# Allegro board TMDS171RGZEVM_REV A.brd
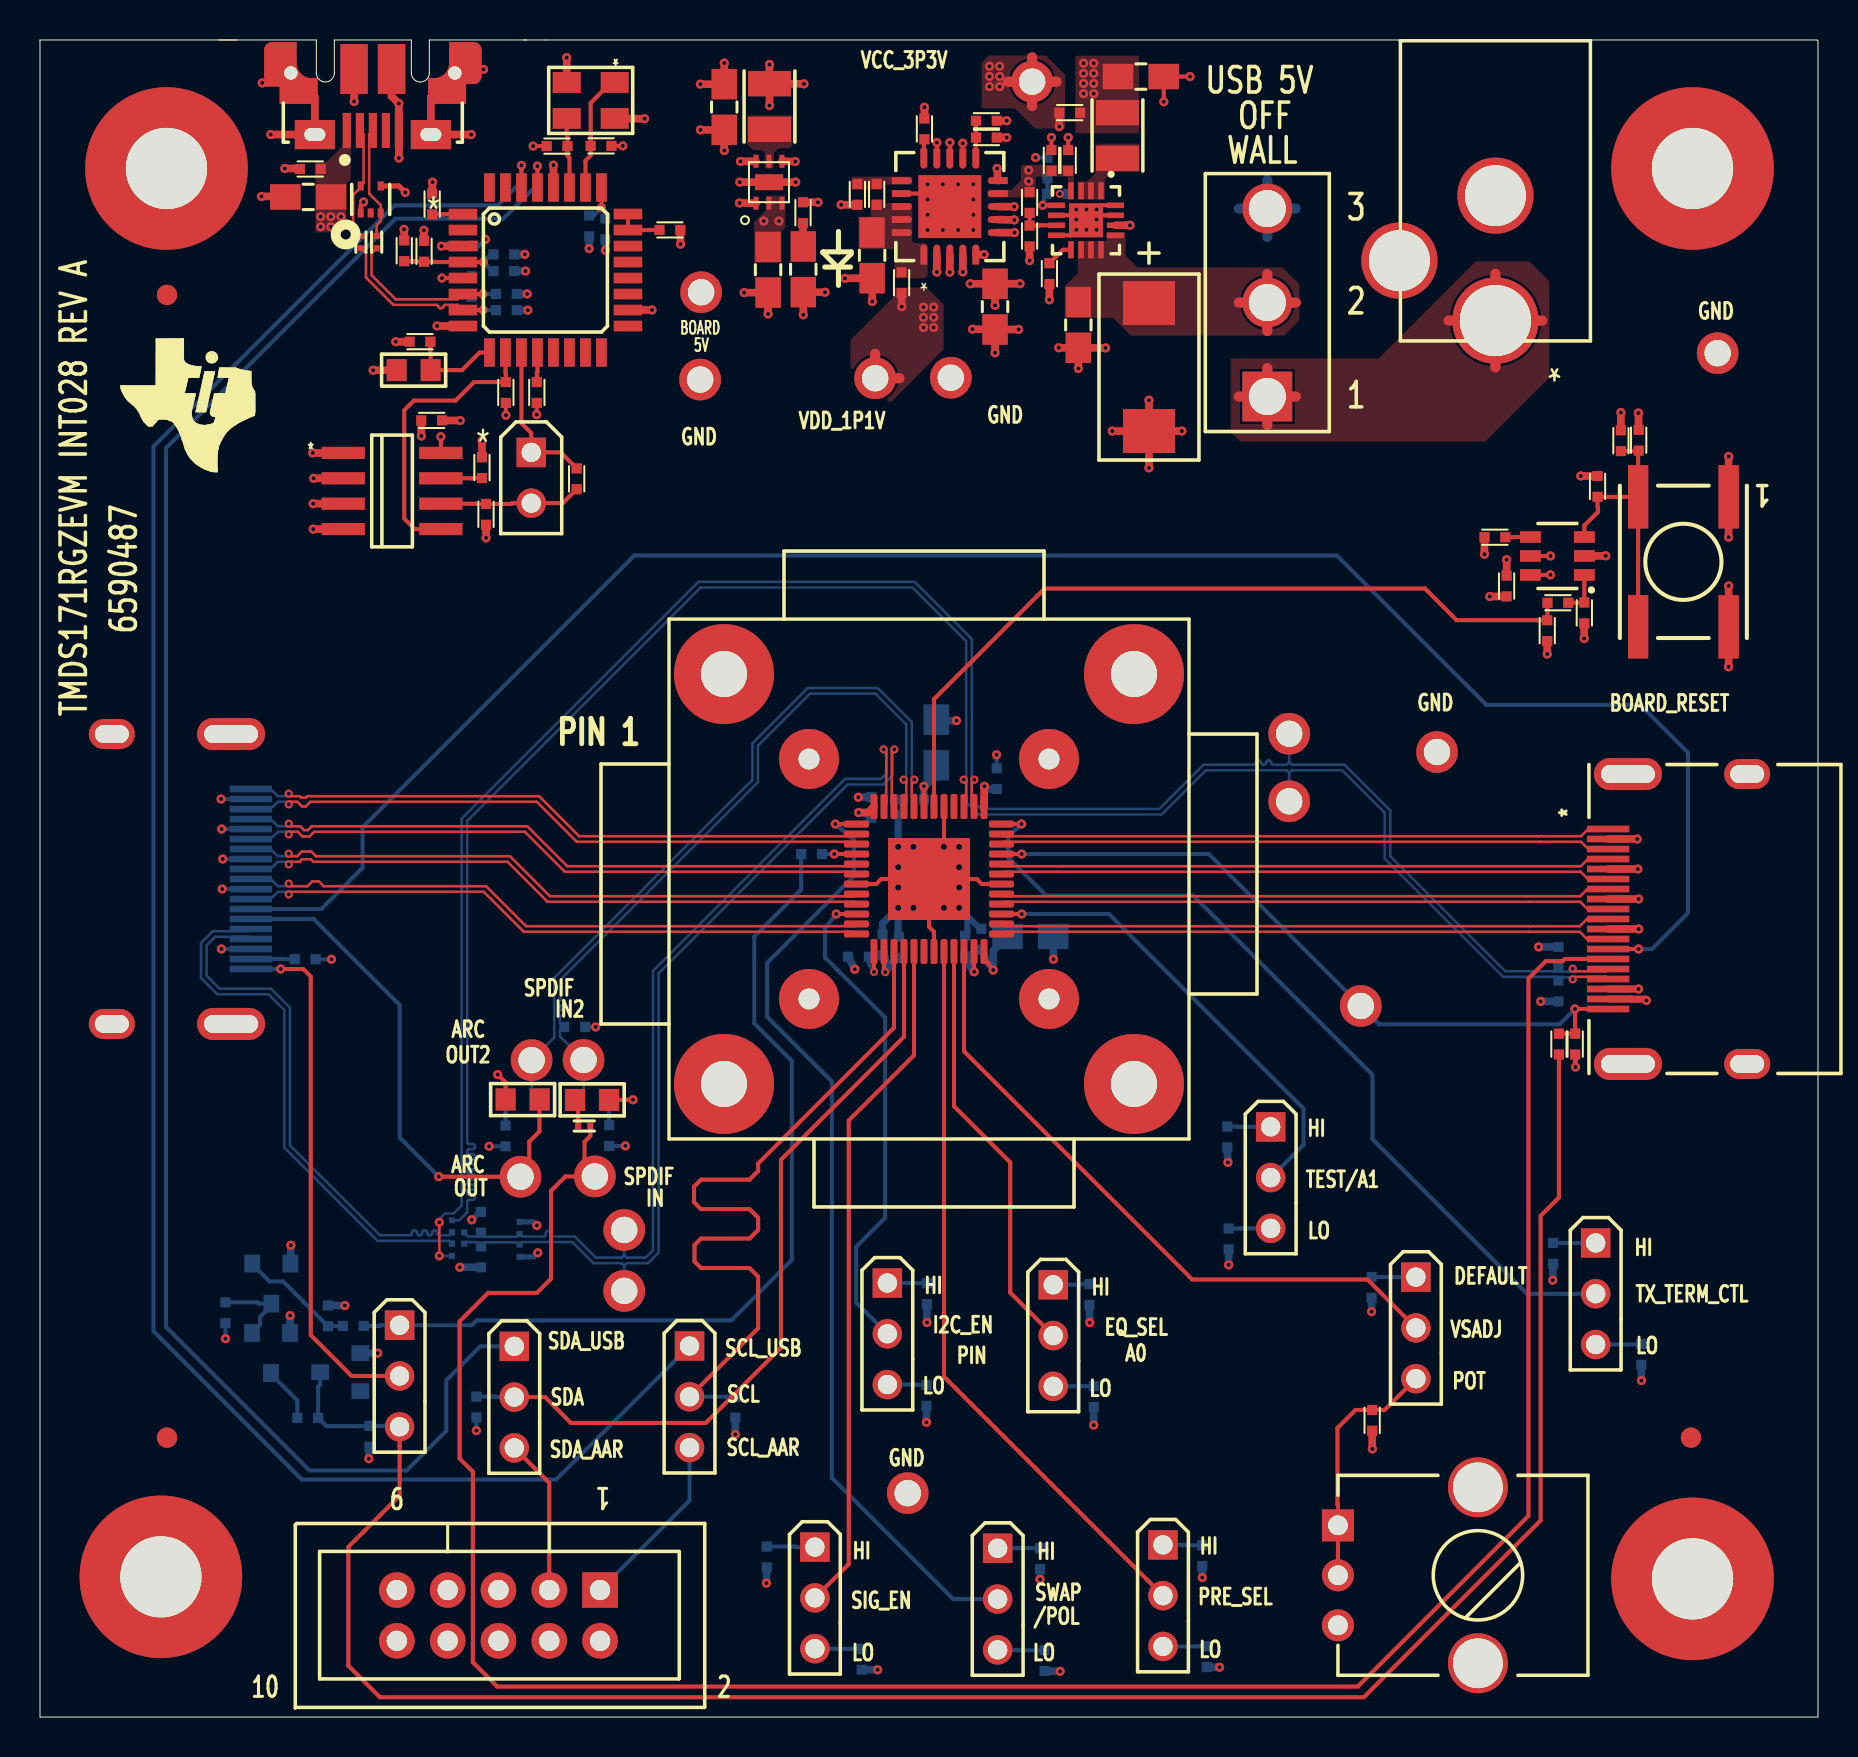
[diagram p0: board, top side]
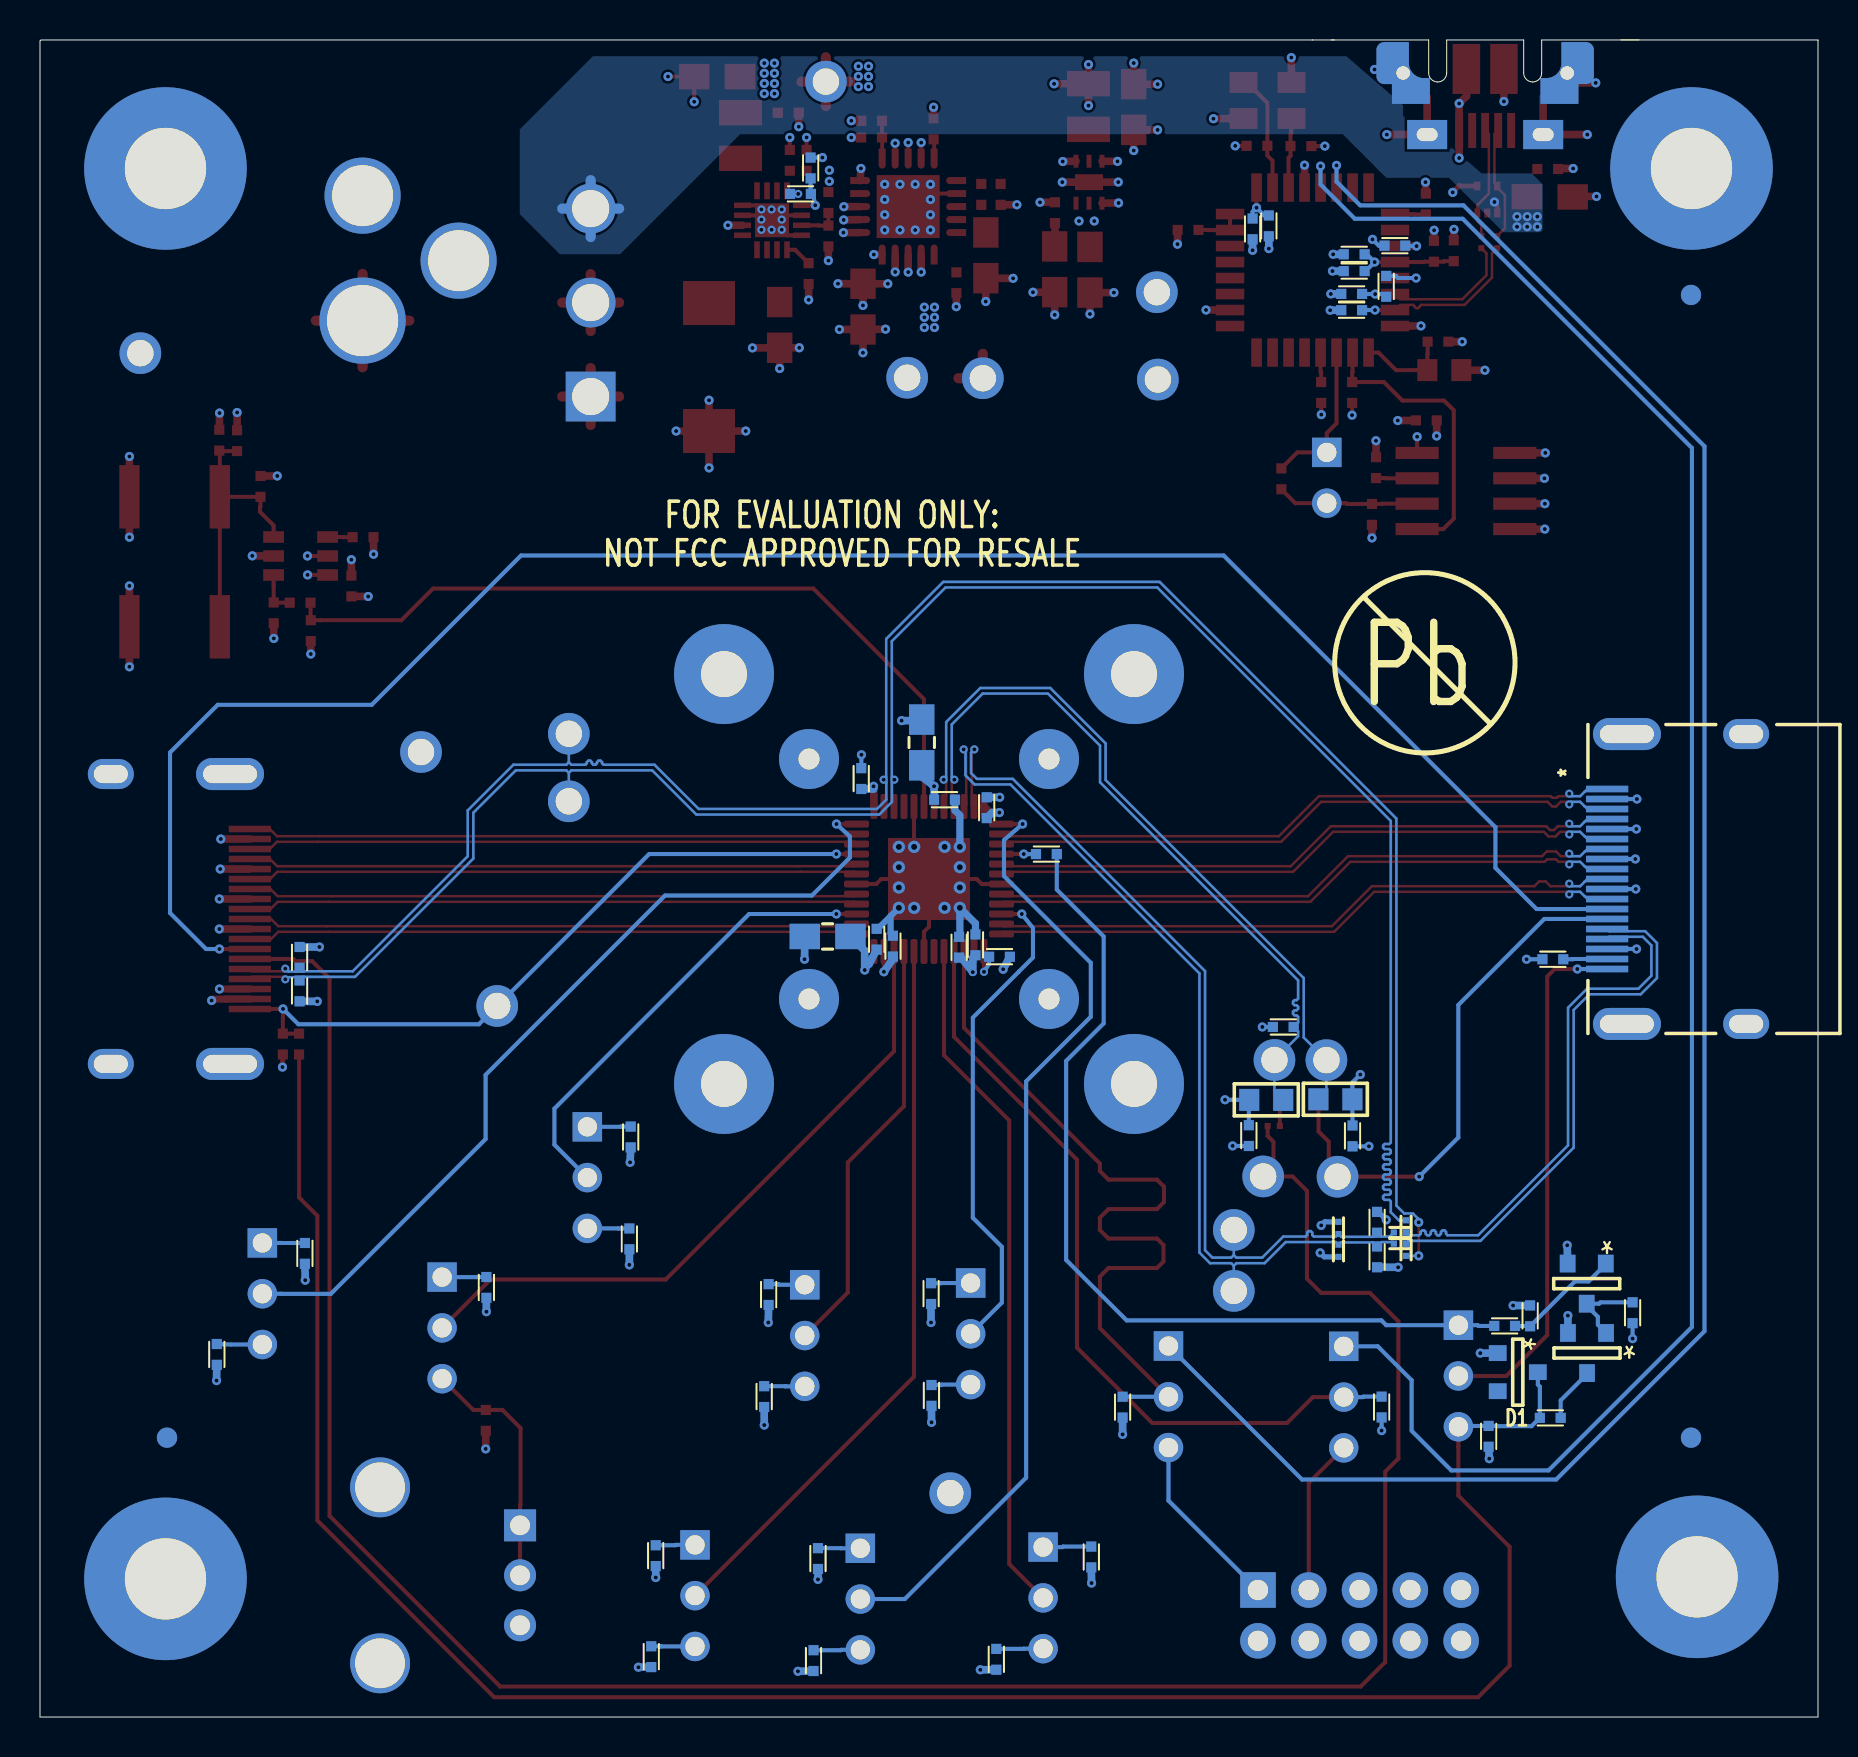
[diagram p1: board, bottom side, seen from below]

Outline 88.9 x 83.87 mm; copper layers: TOP, L2, L3, L4, L5, BOTTOM. Coordinates in mm from the lower left corner of the outline.
Outline path: 9.85,83.87 0,83.87 0,0 88.9,0 88.9,83.82 88.85,83.87 25.25,83.87 ; 25.3,83.87 24.18,83.87

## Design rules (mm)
net group DIFFPAIR12: nets OUT_D2N OUT_D2P
net group DIFFPAIR13: nets OUT_D1N OUT_D1P
net group DIFFPAIR14: nets OUT_D0N OUT_D0P
net group DIFFPAIR15: nets OUT_CLKN OUT_CLKP
net group DIFFPAIR16: nets IN_D0N IN_D0P
net group DIFFPAIR17: nets IN_D1N IN_D1P
net group DIFFPAIR18: nets IN_D2N IN_D2P
net group DIFFPAIR19: nets IN_CLKN IN_CLKP
net group DIFFPAIR24: nets SCL_SRC SDA_SRC
net group DIFFPAIR25: nets HDMI_SCL_SRC HDMI_SDA_SRC
net group DIFFPAIR27: nets N16919318 N16919400
net group DIFFPAIR29: nets AUX_SRCN/ARC_OUT AUX_SRCP/SPDIF_IN
net group DP1: nets N17024118 N17024121
net group DP2: nets HDMI_SCL_SRC_IN HDMI_SDA_SRC_IN
net group DIFF_PAIR 100 OHM_PH: nets EQ_SEL_A0 HDMI_SEL#_TEST_A1 I2C_EN_PIN OE PRE_SEL SCL_CTL_USB SDA_CTL_USB SIG_EN SWAP/POL TX_TERM_CTL VSADJ
nets with their own width: min track width 0.203; nets X2

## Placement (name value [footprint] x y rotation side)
C4  1 uF  [0603]  24.98 30.89 180 bottom
C5  1 uF  [0603]  26.74 30.86 0 bottom
C6  1 uF  [0603]  24.98 30.88 180 top
C7  1 uF  [0603]  28.46 30.86 180 top
C8  10uF  [0805]  44.81 48.74 90 bottom
C9  0.1uF  [0402]  40.93 38.02 180 bottom
C10  0.1uF  [0402]  43.67 45.88 180 bottom
C17  0.1uF  [0402]  47.07 38.9 90 bottom
C18  0.1uF  [0402]  41.56 45.48 90 bottom
C19  0.1uF  [0402]  46.25 38.55 90 bottom
C20  10uF  [0805]  49.52 39.04 0 bottom
C21  0.1uF  [0402]  42.95 38.5 90 bottom
C22  0.01uF  [0402]  42.13 38.62 90 bottom
C23  0.1uF  [0402]  47.84 46.93 90 bottom
C26  DNI_200nF  [0402]  75.36 54.33 270 top
C27  18pF  [0402]  79.04 63.83 90 top
C28  220pF  [0402]  72.75 59 180 top
C29  0.1uF  [0402]  73.33 56.57 270 top
C30  330uF  [7343]  55.45 70.71 270 top
C31  10uF  [0805]  51.92 69.62 270 top
C32  22uF  [0805]  55.04 82.04 0 top
C34  3.3 nF  [0402]  50.47 72.19 270 top
C35  10uF  [0805]  47.75 70.54 270 top
C36  10uF  [0805]  41.61 73.1 270 top
C37  0.01uF  [0402]  47.32 78.99 0 top
C38  DNI  [0402]  44.22 79.43 90 top
C39  2.2uF  [0805]  13.41 76.02 180 top
C40  0.1uF  [0402]  27.46 74.57 90 bottom
C41  0.01uF  [0402]  28.27 74.42 90 bottom
C42  0.01uF  [0402]  21.16 73.58 180 bottom
C45  22pF  [0402]  23.32 71.17 0 bottom
C46  0.1uF  [0402]  23.19 73.15 180 bottom
C47  0.01uF  [0402]  23.19 72.31 180 bottom
C49  22pF  [0402]  23.32 70.36 180 bottom
C50  33pF  [0402]  28.05 78.58 0 top
C51  33pF  [0402]  25.85 78.56 180 top
C52  1 uF  [0603]  17.83 67.36 0 top
C57  10uF  [0805]  36.4 72.38 270 top
C58  2.2uF - DNI  [0805]  34.21 80.52 270 top
C59  0.1uF  [0402]  19.58 64.85 0 top
C60  0.1uF  [0402]  13.51 77.42 180 top
D1  Zener 6V  [SOT_23_321]  15.01 17.25 270 bottom
D2  LED Green 0805  [0805]  38.16 72.4 270 top
J1  HDR3X1 M .1  [HDR_THVT_1X3_100]  17.98 19.6 0 top
J3  HDR3X1 M .1  [HDR_THVT_1X3_100]  42.37 21.7 0 top
J4  HDR3X1 M .1  [HDR_THVT_1X3_100]  32.48 18.55 0 top
J5  Header 5x2 0.1" thru-hole  [CON_THVT_SHRD_2X5_100_M]  20.38 5.08 180 top
J6  HDR3X1 M .1  [HDR_THVT_1X3_100]  23.71 18.54 0 top
J7  HDR3X1 M .1  [HDR_THVT_1X3_100]  61.53 29.52 0 top
J8  HDR3X1 M .1  [HDR_THVT_1X3_100]  68.8 22 0 top
J9  2.1mm x 5.5mm  [PJ-202AH]  72.77 69.84 180 top
J11  HDR3X1 M .1  [HDR_THVT_1X3_100]  38.75 8.5 0 top
J12  HDR3X1 M .1  [HDR_THVT_1X3_100]  50.66 21.62 0 top
J13  USB Micro B  [USB_SMRT_MICRO-B_FCI]  16.64 82.22 180 top
J14  HDR3X1 M .1  [HDR_THVT_1X3_100]  77.78 23.71 0 top
J15  HDR3X1 M .1  [HDR_THVT_1X3_100]  56.15 8.61 0 top
J17  HDR3X1 M .1  [HDR_THVT_1X3_100]  47.88 8.44 0 top
JP1  JUMPER  [HDR_THVT_1X2_100]  24.56 63.25 0 top
L1  2.2 uH  [IND_1008]  53.87 79.1 90 top
L2  1 uH - DNI  [IND_1008]  36.47 80.54 270 top
LP1  LP  [TESTLOOP]  24.58 32.85 0 top
LP2  LP  [TESTLOOP]  27.18 32.86 180 top
LP3  LP  [TESTLOOP]  24.02 27.02 0 top
LP4  LP  [TESTLOOP]  27.74 27.04 180 top
LP5  LP  [TESTLOOP]  49.61 81.79 0 top
LP6  LP  [TESTLOOP]  41.76 66.95 0 top
LP7  LP  [TESTLOOP]  45.54 66.98 0 top
LP8  LP  [TESTLOOP]  69.85 48.26 0 top
LP9  LP  [TESTLOOP]  43.39 11.2 0 top
LP10  LP  [TESTLOOP]  62.46 49.17 0 top
LP11  LP  [TESTLOOP]  62.46 45.8 0 top
LP12  LP  [TESTLOOP]  33.06 71.26 0 top
LP13  LP  [TESTLOOP]  66.04 35.56 0 top
LP14  LP  [TESTLOOP]  33.01 66.89 0 top
LP15  LP  [TESTLOOP]  29.21 21.31 0 top
LP16  LP  [TESTLOOP]  29.21 24.36 0 top
LP17  LP  [TESTLOOP]  83.88 68.21 0 top
NOREF  -  []  9.87 -39.35 0 top
NOREF#2  -  [unnamed#2]  6.32 77.44 0 top
NOREF#3  -  [unnamed#2]  82.63 77.44 0 top
NOREF#4  -  [unnamed#2]  6.05 7.01 0 top
NOREF#5  -  []  0 0 90 top
NOREF#6  -  [unnamed#2]  82.63 6.91 0 top
NOREF#7  -  [unnamed#2]  82.55 13.97 0 top
NOREF#8  -  [unnamed#2]  6.35 13.97 0 top
NOREF#9  -  []  4.01 62.26 0 top
NOREF#10  -  []  0 0 0 top
NOREF#11  -  [unnamed#2]  6.35 71.12 0 top
NOREF#12  -  [unnamed#2]  6.35 71.12 180 bottom
NOREF#13  -  [unnamed#2]  6.35 13.97 180 bottom
NOREF#14  -  []  78.45 61.77 180 bottom
NOREF#15  -  []  19.66 52.72 180 bottom
NOREF#16  -  [unnamed#2]  82.55 13.97 180 bottom
P1  HDMI_IN  [CON_HDMI_SD-47151-001]  10.54 41.91 90 bottom
P2  HDMI_OUT  [CON_HDMI_SD-47151-001]  78.41 39.91 90 top
Q1  FDV301N_NFET_8V  [SOT_23_321]  11.56 21.67 0 bottom
Q2  FDV301N_NFET_8V  [SOT_23_321]  11.55 18.2 0 bottom
R5  100  [0402]  15.67 19.56 180 bottom
R10  1K  [0402]  16.47 14.04 270 bottom
R11  1K  [0402]  9.27 20.22 270 bottom
R12  100K  [0402]  14.39 20.06 270 bottom
R13  10  [0402]  13.39 14.96 0 bottom
R16  47K  [0402]  22.05 23.01 270 bottom
R17  47K  [0402]  22.05 24.74 90 bottom
R24  0  [0201]  20.9 23.67 180 bottom
R25  0  [0201]  20.9 24.23 180 bottom
R34  0  [0201]  27.21 29.56 180 top
R35  DNI  [0402]  23.27 29.06 90 bottom
R36  75  [0402]  28.46 29.08 90 bottom
R45  47K  [0402]  75.92 37.99 90 bottom
R46  47K  [0402]  75.92 36.31 270 bottom
R57  65K  [0402]  44.35 21.17 90 bottom
R58  2K  [0402]  34.77 15.5 90 bottom
R59  2K  [0402]  21.82 15.5 90 bottom
R60  65K  [0402]  44.33 16.08 270 bottom
R61  65K  [0402]  50 7.92 90 bottom
R62  65K  [0402]  50.22 2.82 270 bottom
R63  65K  [0402]  58.11 8.07 90 bottom
R64  65K  [0402]  58.34 3.02 270 bottom
R66  65K  [0402]  59.37 29.01 90 bottom
R68  65K  [0402]  52.47 21.13 90 bottom
R69  65K  [0402]  59.43 23.91 270 bottom
R70  65K  [0402]  52.69 16.02 270 bottom
R71  65K  [0402]  36.34 8 90 bottom
R72  65K  [0402]  75.66 23.19 90 bottom
R73  65K  [0402]  41.08 2.89 270 bottom
R74  65K  [0402]  80.06 18.13 270 bottom
R75  7K  [0402]  66.58 21.48 90 bottom
R76  PTV09 10K POT-DNI  [VAR_RES_THVT_PTV09A-1_123]  64.9 7.09 270 top
R77  0  [0402]  75.9 55.73 0 top
R78  10K  [0402]  77.22 55.22 90 top
R79  4.7K  [0402]  79.93 63.86 270 top
R80  0  [0402]  77.88 61.54 90 top
R81  100K  [0402]  51.41 77.85 270 top
R82  500  [0402]  38.15 75.23 90 top
R83  0  [0402]  49.48 75.74 90 top
R84  0  [0402]  51.49 80.24 0 top
R85  750K  [0402]  50.37 77.47 90 bottom
R86  240K  [0402]  50.88 76.17 180 bottom
R87  DNI  [0402]  50.57 77.85 270 top
R88  4.7K  [0402]  47.32 79.83 180 top
R89  0  [0402]  43.08 71.73 90 top
R90  1.87K  [0402]  41.83 76.15 270 top
R91  4.42K  [0402]  40.87 76.15 90 top
R92  DNI  [0402]  18.21 73.33 90 top
R93  DNI  [0402]  19.2 73.3 270 top
R94  1.5K  [0402]  21.59 71.55 270 bottom
R95  33  [0201]  16.05 73.76 90 top
R96  33  [0201]  16.83 73.76 90 top
R98  10K  [0402]  31.5 74.37 180 top
R99  1K  [0402]  23.29 66.24 90 top
R100  1K  [0402]  22.3 60.15 90 top
R101  1K  [0402]  19.61 75.67 90 top
R102  10K  [0402]  24.84 66.24 90 top
R103  15K  [0402]  19 68.78 0 top
R104  0  [0402]  13.26 37.9 180 bottom
R115  47K - DNI  [0402]  66.61 14.84 270 top
R120  DNI  [0402]  49.48 74.07 270 top
R121  1K  [0402]  22.1 62.48 90 top
R122  0  [0402]  26.83 61.92 270 top
R123  0  [0201]  20.6 24.54 90 bottom
R124  0  [0201]  20.6 23.37 270 bottom
R125  0  [0201]  23.98 24.46 90 bottom
R126  0  [0201]  23.98 23.32 270 bottom
R127  500K  [0402]  26.74 34.51 180 bottom
R129  0  [0402]  75.95 33.66 270 top
R130  1K  [0402]  76.76 33.66 270 top
R131  0  [0402]  38.58 43.16 180 bottom
SW1  PB_SWITCH  [SW_MOM_2NO]  82.17 57.77 180 top
SW2  3POS - SPDT  [SW_THVT_SPDT_3_185P]  61.37 70.74 0 top
U1  TMDS181RGZ  [RGZ48_GRYPHICS_48QFN07-0P5]  44.45 41.91 0 top
U3  TPS3808  [DBV_R-PDSO-G6]  75.87 58.06 180 top
U4  TPS62150A  [RGT_QFN-16]  52.3 74.85 270 top
U5  TPS74201RGWT  [QFN_20_203X203_26]  45.49 75.54 90 top
U6  TPS61240 - DNI  [DRV_S-PWSON-N6]  36.45 76.76 90 top
U7  TUSB3410  [PQFP_32_7P2X7P2_P8MM]  25.27 72.36 0 top
U8  24LC256  [SOIC_8_197X157_50]  17.6 61.32 0 top
U16  TPD2E001  [DRL_PSDO_5]  16.54 75.9 90 top
Y1  12 MHz  [XTAL_4_SM_126X98]  27.53 80.85 180 top

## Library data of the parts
C4-C10 C17-C23 C26-C29 C31 C32 C34 C37-C42 C45-C47 C49-C52 C57-C60 = CAP NP
C30 = CAPACITOR POL
C35 C36 = CAP_0
D1 = Zener 6V
D2 = DIODE
J1 J3 J4 J6-J8 J11 J12 J14 J15 J17 = HDR3X1 M _2.1
J5 = CONN PCB 5x2-S
J9 = BNC_2
J13 = USB Mini AB_1
JP1 = JUMPER
L1 L2 = INDUCTOR
LP1-LP17 = TESTLOOP
P1 P2 = CONN HDMI TYPE A
Q1 Q2 = FDV301N_NFET_8V
R5 R10-R13 = r0402
R16 R17 R24 R25 R34-R36 R45 R46 R57 R61-R64 R66 R68-R75 R77-R81 R83-R87 R89 R92-R96 R98-R104 R115 R120-R127 R129-R131 = R
R58-R60 R82 R88 R90 R91 = R_4
R76 = POT
SW1 = PB_SWITCH_0
SW2 = SW_SLIDE_SPDT2
U1 = DP159RGZ_8
U3 = TPS3808DBV
U4 = TPS62150A
U5 = TPS74401RGWT_1
U6 = TPS61420
U7 = TUSB3410_3
U8 = I2C_0
U16 = TPD2E001-Q1
Y1 = CRYSTAL14_0

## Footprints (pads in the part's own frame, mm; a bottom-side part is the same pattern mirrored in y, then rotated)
0201
  rect 0.305x0.305 smd: 1(-0.305,0) 2(0.305,0)
0402
  rect 0.508x0.508 smd: 1(-0.521,0) 2(0.521,0)
0603
  rect 1x1.1 smd: 1(0,0) 2(1.7,0)
0805
  rect 1.524x1.27 smd: 1(-1.143,0) 2(1.143,0)
7343
  rect 2.2x2.6 smd: 1(0,0) 2(6.4,0)
CON_HDMI_SD-47151-001
  rect 0.33x2.11 smd: 1(4.501,0) 2(4,0) 3(3.5,0) 4(3,0) 5(2.499,0) 6(1.999,0) 7(1.501,0) 8(1.001,0) 9(0.5,0) 10(0,0) 11(-0.5,0) 12(-1.001,0) 13(-1.501,0) 14(-1.999,0) 15(-2.499,0) 16(-3,0) 17(-3.5,0) 18(-4,0) 19(-4.501,0)
  oval 1.6x3.4 hole 0.9x2.7: 20(-7.248,-0.99) 21(7.25,-0.99)
  oval 1.5x2.3 hole 0.9x1.7: 22(7.25,-6.951) 23(-7.248,-6.951)
CON_THVT_SHRD_2X5_100_M
  rect 1.778x1.778 hole 1.016: 1(-7.62,-1.27)
  round 1.778 hole 1.016: 2(-7.62,1.27) 3(-5.08,-1.27) 4(-5.08,1.27) 5(-2.54,-1.27) 6(-2.54,1.27) 7(0,-1.27) 8(0,1.27) 9(2.54,-1.27) 10(2.54,1.27)
DBV_R-PDSO-G6
  rect 1.041x0.584 smd: 1(-1.35,0.95) 2(-1.35,0) 3(-1.35,-0.95) 4(1.35,-0.95) 5(1.35,0) 6(1.35,0.95)
DRL_PSDO_5
  rect 0.45x0.3 smd: 1(-0.675,0.5) 2(-0.675,0) 3(-0.675,-0.5) 4(0.675,-0.5) 5(0.675,0.5)
DRV_S-PWSON-N6
  rect 0.65x0.25 smd: 1(-1.05,0.65) 2(-1.05,0) 3(-1.05,-0.65) 4(1.05,-0.65) 5(1.05,0) 6(1.05,0.65)
  rect 0.8x1.4 smd: 7(0,0)
HDR_THVT_1X2_100
  rect 1.473x1.473 hole 0.965: 1(0,0)
  round 1.473 hole 0.965: 2(0,-2.54)
HDR_THVT_1X3_100
  rect 1.473x1.473 hole 0.965: 1(0,0)
  round 1.473 hole 0.965: 2(0,-2.54) 3(0,-5.08)
IND_1008
  rect 1.27x2.146 smd: 1(-1.143,0) 2(1.143,0)
PJ-202AH
  round 4.318 hole 3.556: 1(0,0)
  round 3.81 hole 3.048: 2(4.801,-2.997) 3(0,-6.248)
PQFP_32_7P2X7P2_P8MM
  rect 1.422x0.533 smd: 1(-4.125,2.8) 2(-4.125,2) 3(-4.125,1.2) 4(-4.125,0.4) 5(-4.125,-0.4) 6(-4.125,-1.2) 7(-4.125,-2) 8(-4.125,-2.8) 17(4.125,-2.8) 18(4.125,-2) 19(4.125,-1.2) 20(4.125,-0.4) 21(4.125,0.4) 22(4.125,1.2) 23(4.125,2) 24(4.125,2.8)
  rect 0.533x1.422 smd: 9(-2.8,-4.125) 10(-2,-4.125) 11(-1.2,-4.125) 12(-0.4,-4.125) 13(0.4,-4.125) 14(1.2,-4.125) 15(2,-4.125) 16(2.8,-4.125) 25(2.8,4.125) 26(2,4.125) 27(1.2,4.125) 28(0.4,4.125) 29(-0.4,4.125) 30(-1.2,4.125) 31(-2,4.125) 32(-2.8,4.125)
QFN_20_203X203_26
  custom 0.088x0.088 smd: 1(-2.4,1.3) 2(-2.4,0.65) 3(-2.4,0) 4(-2.4,-0.65) 5(-2.4,-1.3) 6(-1.3,-2.4) 7(-0.65,-2.4) 8(0,-2.4) 9(0.65,-2.4) 10(1.3,-2.4) 11(2.4,-1.3) 12(2.4,-0.65) 13(2.4,0) 14(2.4,0.65) 15(2.4,1.3) 16(1.3,2.4) 17(0.65,2.4) 18(0,2.4) 19(-0.65,2.4) 20(-1.3,2.4)
  rect 3.15x3.15 smd: 21(0,0)
RGT_QFN-16
  rect 0.85x0.28 smd: 1(-1.475,0.75) 2(-1.475,0.25) 3(-1.475,-0.25) 4(-1.475,-0.75) 9(1.475,-0.75) 10(1.475,-0.25) 11(1.475,0.25) 12(1.475,0.75)
  rect 0.28x0.85 smd: 5(-0.75,-1.475) 6(-0.25,-1.475) 7(0.25,-1.475) 8(0.75,-1.475) 13(0.75,1.475) 14(0.25,1.475) 15(-0.25,1.475) 16(-0.75,1.475)
  rect 1.7x1.7 smd: 17(0,0)
RGZ48_GRYPHICS_48QFN07-0P5
  round 5 hole 2.3: (-10.25,10.25) (-10.25,-10.25) (10.25,10.25) (10.25,-10.25)
  round 3 hole 1.05 unplated: (-6,6) (-6,-6) (6,6) (6,-6)
  custom 0.088x0.088 smd: 1(-3.625,2.75) 2(-3.625,2.25) 3(-3.625,1.75) 4(-3.625,1.25) 5(-3.625,0.75) 6(-3.625,0.25) 7(-3.625,-0.25) 8(-3.625,-0.75) 9(-3.625,-1.25) 10(-3.625,-1.75) 11(-3.625,-2.25) 12(-3.625,-2.75) 13(-2.75,-3.625) 14(-2.25,-3.625) 15(-1.75,-3.625) 16(-1.25,-3.625) 17(-0.75,-3.625) 18(-0.25,-3.625) 19(0.25,-3.625) 20(0.75,-3.625) 21(1.25,-3.625) 22(1.75,-3.625) 23(2.25,-3.625) 24(2.75,-3.625) 25(3.625,-2.75) 26(3.625,-2.25) 27(3.625,-1.75) 28(3.625,-1.25) 29(3.625,-0.75) 30(3.625,-0.25) 31(3.625,0.25) 32(3.625,0.75) 33(3.625,1.25) 34(3.625,1.75) 35(3.625,2.25) 36(3.625,2.75) 37(2.75,3.625) 38(2.25,3.625) 39(1.75,3.625) 40(1.25,3.625) 41(0.75,3.625) 42(0.25,3.625) 43(-0.25,3.625) 44(-0.75,3.625) 45(-1.25,3.625) 46(-1.75,3.625) 47(-2.25,3.625) 48(-2.75,3.625)
  rect 4.1x4.1 smd: 49(0,0)
SOIC_8_197X157_50
  rect 2.159x0.61 smd: 1(-2.44,1.905) 2(-2.44,0.635) 3(-2.44,-0.635) 4(-2.44,-1.905) 5(2.44,-1.905) 6(2.44,-0.635) 7(2.44,0.635) 8(2.44,1.905)
SOT_23_321
  rect 0.787x0.889 smd: 1(-0.953,-1.003) 2(0.953,-1.003) 3(0,1.003)
SW_MOM_2NO
  rect 1.016x3.175 smd: 1(-2.261,-3.251) 2(-2.261,3.251) 3(2.261,-3.251) 4(2.261,3.251)
SW_THVT_SPDT_3_185P
  rect 2.489x2.489 hole 1.854: 1(0,-4.7)
  round 2.489 hole 1.854: 2(0,0) 3(0,4.7)
TESTLOOP
  round 2.083 hole 1.321: 1(0,0)
unnamed#2
  round 8.128 hole 4.064: (0,0)
USB_SMRT_MICRO-B_FCI
  rect 0.4x1.75 smd: 1(1.3,2.875) 2(0.65,2.875) 3(0,2.875) 4(-0.65,2.875) 5(-1.3,2.875)
  rect 2x1.46 hole 1.05x0.65: 6(2.9,3.08) 11(-2.9,3.08)
  custom 0.669x0.669 hole 0.7x1.3: 7(4.1,0) 10(-4.1,0)
  rect 1.375x2.5 smd: 8(0.938,-0.2) 9(-0.938,-0.2)
VAR_RES_THVT_PTV09A-1_123
  round 2.997 hole 2.489: (-4.4,7) (4.4,7)
  rect 1.6x1.6 hole 0.991: 1(-2.5,0)
  round 1.6 hole 0.991: 2(0,0) 3(2.5,0)
XTAL_4_SM_126X98
  rect 1.397x1.041 smd: 1(-1.2,-0.9) 2(1.2,-0.9) 3(1.2,0.9) 4(-1.2,0.9)

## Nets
+1V8: C46.2 C47.2 R92.1 R93.2 U7.4(VDD1V8)
GND: C8.2 C9.2 C10.2 C17.2 C18.2 C19.2 C20.2 C21.2 C22.2 C23.2 C26.2 C27.2 C28.2 C29.2 C30.2 C31.2 C32.2 C34.2 C35.2 C36.2 C37.2 C38.2 C39.2 C40.1 C41.1 C42.1 C45.2 C46.1 C47.1 C49.1 C50.2 C51.2 C52.1 C57.2 C58.2 C59.1 C60.2 D1.1 D2.2(K) J5.2(6) J5.10 J9.2(S) J9.3(SW) J13.5(GND) J13.6(S1) J13.7(S2) J13.8(S3) J13.9(S4) J13.10(S5) J13.11(S6) LP7.1 LP8.1 LP9.1 LP14.1 LP17.1 P1.2 P1.5 P1.8 P1.11 P1.17 P1.20(CASE1) P1.21(CASE2) P1.22(CASE3) P1.23(CASE4) P2.2 P2.5 P2.8 P2.11 P2.17 P2.20(CASE1) P2.21(CASE2) P2.22(CASE3) P2.23(CASE4) Q1.2(S) Q2.2(S) R12.1 R35.1 R36.1 R60.2 R62.2 R64.2 R69.2 R70.2 R73.2 R74.2 R75.1 R76.3(B) R86.1 R91.1 R93.1 R101.2 R115.2 R120.2 R121.2 R125.2 R126.2 R127.1 SW1.1(A) SW1.2(A_) U1.7(GND1) U1.19(GND2) U1.30(GND3) U1.41(GND4) U1.49(PAD) U3.2(GND) U4.6(AGND) U4.8(DEF) U4.15(PGND1) U4.16(PGND2) U4.17(PAD) U5.2(NC1) U5.3(NC2) U5.4(NC3) U5.12(GND) U5.13(NC4) U5.14(NC5) U5.17(NC6) U5.21(PAD) U6.1(GND) U6.7(PAD) U7.8(GND1) U7.18(GND2) U7.28(GND3) U8.1(A0) U8.2(A1) U8.3(A2) U8.4(VSS) U16.4(GND) Y1.2 Y1.4
VCC_3P3V: C8.1 C9.1 C10.1 C29.1 LP5.1 R57.1 R58.1 R59.1 R61.1 R63.1 R66.1 R68.1 R71.1 R72.1 R78.1 R84.1 U1.13(VCC1) U1.43(VCC2) U3.5(SENSE) U3.6(VDD)
VDD_1P1V: C17.1 C18.1 C19.1 C20.1 C21.1 C22.1 C23.1 LP6.1 R89.1 U1.14(VDD1) U1.23(VDD2) U1.24(VDD3) U1.37(VDD4) U1.48(VDD5)
ARC_OUT: C6.1 LP3.1 P1.14
AUX_SRCN/ARC_OUT: C4.1 LP1.1 U1.44(AUX_SRCN/ARC_OUT)
AUX_SRCP/SPDIF_IN: C5.1 LP2.1 R127.2 U1.45(AUX_SRCP/SPDIF_IN)
BOARD_1P1V: C36.1 R89.2 R90.2 U5.1(OUT1) U5.18(OUT4) U5.19(OUT3) U5.20(OUT2)
BOARD_3P3V: C32.1 C35.1 C40.2 C41.2 C42.2 C58.1 C59.2 L1.2 L2.1 R79.1 R81.1 R84.2 R85.2 R87.1 R88.1 R92.2 R98.1 R99.1 R100.1 R102.1 R103.1 U4.14(VOS) U5.5(IN1) U5.6(IN2) U5.7(IN3) U5.8(IN4) U5.10(BIAS) U6.4(EN) U6.6(VIN) U7.3(VCC1) U7.25(VCC2) U8.8(VCC)
BOARD_5V: C57.1 LP12.1 P2.18 R10.2 R11.2 R16.2 R17.2 R45.2 R46.2 R82.2 R104.1 R130.2 U6.2(VOUT) U6.3(FB)
BOARD_IN: C30.1 C31.1 SW2.2 U4.10(AVIN) U4.11(PVIN1) U4.12(PVIN2) U4.13(EN)
EN1P2: C37.1 R88.2 U5.11(EN)
EQ_SEL_A0: J12.2 U1.21(EQ_SEL/A0)
EQ_SEL_HI: J12.1 R68.2
EQ_SEL_LO: J12.3 R70.1
FB_1PT2V: R90.1 R91.2 U5.16(FB)
FB_3PT3V: R85.1 R86.2 U4.5(FB)
HDMI_CEC_SNK: P1.13 P2.13
HDMI_IN_5V: P1.18 R104.2
HDMI_SCL_SRC: LP10.1 P2.15 R45.1 R124.2 U1.38(SCL_SNK)
HDMI_SCL_SRC_IN: P1.15 R24.2 R124.1
HDMI_SDA_SRC: LP11.1 P2.16 R46.1 R123.2 U1.39(SDA_SNK)
HDMI_SDA_SRC_IN: P1.16 R25.2 R123.1
HDMI_SEL#_TEST_A1: J7.2 U1.27(HDMI_SEL#/A1)
HPD_SNK: LP13.1 P2.19 R129.1 R130.1 U1.33(HPD_SNK)
HPD_SRC: J1.1 R5.1 R131.2
HPD_SRC_CONN: D1.3 J1.3 R10.1 R13.2 R129.2
HPD_SRC_HDMI_RX_CONN: J1.2 P1.19
I2C_EN_HI: J3.1 R57.2
I2C_EN_LO: J3.3 R60.1
I2C_EN_PIN: J3.2 U1.10(I2C_EN/PIN)
IN_CLKN: P1.12 U1.12(IN_CLKN)
IN_CLKP: P1.10 U1.11(IN_CLKP)
IN_D0N: P1.9 U1.9(IN_D0N)
IN_D0P: P1.7 U1.8(IN_D0P)
IN_D1N: P1.6 U1.6(IN_D1N)
IN_D1P: P1.4 U1.5(IN_D1P)
IN_D2N: P1.3 U1.3(IN_D2N)
IN_D2P: P1.1 U1.2(IN_D2P)
OE: C26.1 R77.1 U1.42(OE)
OUT_CLKN: P2.12 U1.25(OUT_CLKN)
OUT_CLKP: P2.10 U1.26(OUT_CLKP)
OUT_D0N: P2.9 U1.28(OUT_D0N)
OUT_D0P: P2.7 U1.29(OUT_D0P)
OUT_D1N: P2.6 U1.31(OUT_D1N)
OUT_D1P: P2.4 U1.32(OUT_D1P)
OUT_D2N: P2.3 U1.34(OUT_D2N)
OUT_D2P: P2.1 U1.35(OUT_D2P)
PB_MANUAL_RESET: C27.1 R79.2 R80.1 SW1.3(B_) SW1.4(B) U3.3(MR#)
PRE_SEL: J15.2 U1.20(PRE_SEL)
PRE_SEL_HI: J15.1 R63.2
PRE_SEL_LO: J15.3 R64.1
PWRIN_SW: J9.1(T) SW2.1
REG_PG: R80.2 R81.2 R83.2 R87.2 U4.4(PG) U5.9(PG)
RSTIN: C52.2 R103.2 U7.9(\\R\E\S\E\T\)
SCL_CTL: J4.2 R58.2 U1.15(SCL_CTL)
SCL_CTL_USB: J4.1 U7.30(P3_3)
SCL_SRC: LP15.1 R16.1 R24.1 R126.1 U1.46(SCL_SRC)
SDA_CTL: J6.2 R59.2 U1.16(SDA_CTL)
SDA_CTL_USB: J6.1 U7.29(P3_4)
SDA_SRC: LP16.1 R17.1 R25.1 R125.1 U1.47(SDA_SRC)
SIG_EN: J11.2 U1.17(SIG_EN)
SIG_EN_HI: J11.1 R71.2
SIG_EN_LO: J11.3 R73.1
SPDIF_IN: LP4.1 P2.14 R34.1
SS1P2: C38.1 U5.15(SS)
SWAP/POL: J17.2 U1.1(SWAP/POL)
SWAP_POL_HI: J17.1 R61.2
SWAP_POL_LO: J17.3 R62.1
TPS3808_CT: C28.1 U3.4(CT)
TX_TERM_CTL: J14.2 U1.36(TX_TERM_CTL)
TX_TERM_CTL_HI: J14.1 R72.2
TX_TERM_CTL_LO: J14.3 R74.1
USB_5V: C39.1 C60.1 J13.1(VBUS) SW2.3 U16.1(VCC)
VSADJ: J8.2 U1.22(VSADJ)
X1: C51.1 U7.27(X1/CLKI) Y1.3
X2: C50.1 U7.26(X2) Y1.1
N16782838: R77.2 R78.2 U3.1(RESET#)
N16874758: J7.1 R66.2
N16874763: J7.3 R69.1
N16881139: J5.3(2) J6.3
N16881148: J4.3 J5.1
N16883754: J8.1 R75.2
N16883759: J8.3 R76.1(A) R76.2(WIPER) R115.1
N16887406: R102.2 U7.12(\\W\A\K\E\U\P\)
N16892757: Q1.1(G) R5.2 R12.2
N16892765: Q1.3(D) Q2.1(G) R11.1
N16892877: Q2.3(D) R13.1
N16906083: C5.2 C7.1 R36.2
N16910161: C4.2 C6.2 R35.2
N16916452: JP1.1 R122.1 U7.11(SCL)
N16916458: JP1.2 R100.2 R122.2 U8.6(SCL)
N16916991: R99.2 U7.10(SDA) U8.5(SDA)
N16919313: R94.1 U7.5(PUR)
N16919318: C45.1 R94.2 R96.1 U7.6(DP0)
N16919400: C49.2 R95.1 U7.7(DM0)
N16919998: R101.1 U7.1(\\V\R\E\G\E\N\)
N16928867: C7.2 R34.2
N16962991: L2.2 U6.5(L)
N16965307: R83.1 R120.1 U4.7(FSW)
N16965311: L1.1 U4.1(SW1) U4.2(SW2) U4.3(SW3)
N16965335: C34.1 U4.9(SS/TR)
N16968702: R98.2 U7.23(TEST0) U7.24(TEST1)
N16982334: R121.1 U8.7(WP)
N17019193: R131.1 U1.4(HPD_SRC)
N17024118: J13.2(DM) R95.2 U16.5(IO2)
N17024121: J13.3(DP) R96.2 U16.3(IO1)
N169633680: D2.1(A) R82.1

Pads without a net: D1 2; J5 4 5 6 7 8 9; J13 4; U1 18 40; U7 2 13 14 15 16 17 19 20 21 22 31 32; U16 2

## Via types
v1: diameter 0.457, hole 0.203, TOP to BOTTOM, 235 vias
v2: diameter 0.406, hole 0.203, TOP to BOTTOM, 27 vias
v3: diameter 0.61, hole 0.305, TOP to BOTTOM, 12 vias

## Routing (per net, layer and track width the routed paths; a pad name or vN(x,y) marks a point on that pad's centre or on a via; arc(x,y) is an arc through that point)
+1V8: length 5.3
  TOP w0.203: R92.1 18.69,72.81 18.72,72.78 R93.2 19.68,72.78 19.7,72.76 U7.4 v1(22.17,72.76)
  BOTTOM w0.203: C46.2 22.56,73.15 v1(22.17,72.76) 22.62,72.31 C47.2
GND: length 376
  TOP w0.203: U4.6 52.05,75.1 U4.17 ; U5.12 v1(46.14,78.71) ; v1(56.19,80.78) C32.2 v1(57.5,82.04) ; U1.49 42.06,41.91 41.81,41.66 U1.7 ; U1.49 45.2,42.66 U1.41 ; U1.49 46.84,41.91 47.09,41.66 U1.30 ; U1.49 44.45,39.52 44.7,39.27 U1.19 ; 52.55,75.1 U4.17 ; 52.55,75.1 53.05,75.6 U4.16 ; 52.55,75.1 U4.15 ; U4.17 51.55,74.1 U4.8 ; U5.14 v1(44.84,78.74) ; C50.2 v1(29.14,78.58) ; U5.13 v1(45.49,78.74) ; C51.2 v1(24.66,78.56) ; U5.17 44.84,76.19 U5.21
  TOP w0.254: v1(18.26,76.25) 17.94,76.57 U16.4
  TOP w0.356: P2.17 v1(79.93,36.41)
  TOP w0.381: v1(38.16,70.13) D2.2 v1(39.25,71.25) ; v1(40.25,71.95) C36.2 v1(41.61,70.79) ; C37.2 v1(48.34,78.99) ; C31.2 v1(50.94,68.48) ; C31.2 v1(51.92,67.44) ; C31.2 v1(53.28,68.47) ; C30.2 v1(57.1,64.31) ; C30.2 v1(53.61,64.31) ; C30.2 v1(55.45,65.85) ; C30.2 v1(55.45,62.47) ; C38.2 v1(44.22,80.51) ; v1(35.2,71.24) C57.2 v1(36.4,70.17) ; J13.8 v1(15.7,80.8) ; R121.2 v1(22.1,63.83) ; v1(84.43,56.57) SW1.2 v1(84.43,52.52) ; C34.2 v1(50.47,70.88) ; P2.11 v1(79.94,39.41) ; U7.28 v1(25.67,77.61) ; U8.4 v1(13.66,59.41) ; Y1.4 v1(30.23,79.93) ; C26.2 v1(75.36,53.16) ; v1(84.43,59.01) SW1.1 v1(84.43,63.04) ; v1(22.17,82.4) 20.92,82.4 J13.10 19.54,81.02 J13.11 v1(21.56,79.14) ; U3.2 v1(78.29,58.07) ; C60.2 12.97,77.44 v1(12.24,77.44) ; U8.2 v1(13.68,61.95) ; C35.2 v1(47.75,68.23) ; C35.2 v1(46.62,69.41) ; C35.2 v1(48.93,69.4) ; Y1.2 v1(26.33,82.99) ; R115.2 v1(66.62,13.41) ; v1(11.07,76.05) 12.24,76.05 C39.2 ; v1(33.02,79.38) C58.2 v1(34.21,78.34) ; P2.2 v1(79.86,43.91) ; C27.2 v1(79.04,65.24) ; U5.2 v1(44.84,72.26) ; R101.2 19.61,76.25 v1(19.63,76.76) ; U8.1 v1(13.64,63.22) ; v1(37.79,76.76) U6.7 v1(34.99,76.76) ; U8.3 v1(13.66,60.68) ; v1(17.94,77.97) J13.5 v1(17.94,80.7) 17.57,81.06 17.57,82.41 J13.9 ; R120.2 v1(49.48,72.84) ; U7.8 v1(19.85,69.57) ; U5.3 v1(45.49,72.26) ; R91.1 v1(40.06,75.63) ; P2.5 v1(79.89,42.41) ; R93.1 v1(19.19,74.36) ; P2.8 v1(79.93,40.91) ; C59.1 v1(19.07,64.07) ; U6.1 v1(34.97,75.72) ; v1(11.11,81.73) 12.05,81.73 J13.7 13.74,81.02 J13.6 v1(11.54,79.14) ; C28.2 v1(72.22,58.15) ; C52.1 v1(16.65,67.35) ; C29.2 v1(72.49,56.04) ; U5.4 v1(46.14,72.27) ; U7.18 v1(30.6,70.37)
  L2 w0.508: P2.21 79.4,48.14 ; P2.21 79.4,46.18 ; P2.21 77.52,47.16 ; P2.21 81.28,47.16 ; 28,2.74 J5.2 ; J5.2 28,4.88 ; J5.2 29.07,3.81 ; J5.2 26.94,3.81 ; LP14.1 33.01,68.11 ; LP14.1 31.79,66.89 ; LP14.1 34.23,66.89 ; LP14.1 33.01,65.67 ; 44.32,66.98 LP7.1 ; LP7.1 45.54,65.76 ; LP7.1 45.54,68.2 ; LP7.1 46.76,66.98 ; 19.54,78.23 J13.11 ; J13.11 18.36,79.14 ; J13.11 20.72,79.14 ; 77.52,32.66 P2.20 ; P2.20 79.4,33.64 ; P2.20 79.4,31.68 ; P2.20 81.28,32.66 ; 67.97,70.75 J9.2 ; J9.2 65.89,72.83 ; J9.2 70.05,72.83 ; J9.2 67.97,74.92 ; P2.23 86.69,32.66 ; P2.23 85.36,33.59 ; P2.23 85.36,31.73 ; P2.23 84.03,32.66 ; J9.3 74.85,76.09 ; J9.3 70.69,76.09 ; J9.3 72.77,74 ; J9.3 72.77,78.17 ; P1.21 11.43,49.16 ; P1.21 7.68,49.16 ; P1.21 9.55,48.18 ; P1.21 9.55,50.14 ; 17.84,2.74 J5.10 ; J5.10 17.84,4.88 ; J5.10 16.78,3.81 ; J5.10 18.91,3.81 ; LP8.1 71.07,48.26 ; LP8.1 69.85,47.04 ; LP8.1 69.85,49.48 ; LP8.1 68.63,48.26 ; P1.20 11.43,34.66 ; P1.20 9.55,33.68 ; P1.20 9.55,35.64 ; P1.20 7.68,34.66 ; LP9.1 44.61,11.2 ; LP9.1 42.17,11.2 ; LP9.1 43.39,9.98 ; LP9.1 43.39,12.42 ; 82.66,68.21 LP17.1 ; LP17.1 83.88,66.99 ; LP17.1 85.1,68.21 ; LP17.1 83.88,69.43 ; 63.92,4.59 R76.3 ; R76.3 65.88,4.59 ; R76.3 64.9,5.56 ; R76.3 64.9,3.61 ; 3.59,33.73 P1.23 ; P1.23 4.92,34.66 ; P1.23 3.59,35.59 ; P1.23 2.26,34.66 ; P2.22 85.36,48.09 ; P2.22 84.03,47.16 ; P2.22 86.69,47.16 ; P2.22 85.36,46.23 ; J13.6 14.92,79.14 ; J13.6 13.74,78.23 ; J13.6 12.56,79.14 ; P1.22 3.59,50.09 ; P1.22 2.26,49.16 ; P1.22 4.92,49.16 ; P1.22 3.59,48.23 ; 11.71,82.22 J13.7 12.54,80 ; 21.57,82.22 J13.10 20.74,80
  L5 w0.508: 84.03,32.66 P2.23 ; P2.23 85.36,33.59 ; P2.23 86.69,32.66 ; P2.23 85.36,31.73 ; 16.78,3.81 J5.10 ; J5.10 18.91,3.81 ; J5.10 17.84,4.88 ; J5.10 17.84,2.74 ; LP9.1 43.39,12.42 ; LP9.1 42.17,11.2 ; LP9.1 44.61,11.2 ; LP9.1 43.39,9.98 ; 13.74,78.23 J13.6 ; J13.6 12.56,79.14 ; J13.6 14.92,79.14 ; P2.22 85.36,48.09 ; P2.22 84.03,47.16 ; P2.22 86.69,47.16 ; P2.22 85.36,46.23 ; 65.89,72.83 J9.2 ; J9.2 70.05,72.83 ; J9.2 67.97,74.92 ; J9.2 67.97,70.75 ; J9.3 74.85,76.09 ; J9.3 72.77,74 ; J9.3 70.69,76.09 ; J9.3 72.77,78.17 ; P1.20 11.43,34.66 ; P1.20 9.55,35.64 ; P1.20 7.68,34.66 ; P1.20 9.55,33.68 ; 64.9,3.61 R76.3 ; R76.3 63.92,4.59 ; R76.3 65.88,4.59 ; R76.3 64.9,5.56 ; 77.52,32.66 P2.20 ; P2.20 79.4,33.64 ; P2.20 81.28,32.66 ; P2.20 79.4,31.68 ; 18.36,79.14 J13.11 ; J13.11 20.72,79.14 ; J13.11 19.54,78.23 ; P1.21 9.55,50.14 ; P1.21 7.68,49.16 ; P1.21 11.43,49.16 ; P1.21 9.55,48.18 ; 82.66,68.21 LP17.1 ; LP17.1 85.1,68.21 ; LP17.1 83.88,69.43 ; LP17.1 83.88,66.99 ; P1.22 3.59,50.09 ; P1.22 2.26,49.16 ; P1.22 4.92,49.16 ; P1.22 3.59,48.23 ; LP7.1 45.54,68.2 ; LP7.1 46.76,66.98 ; LP7.1 45.54,65.76 ; LP7.1 44.32,66.98 ; LP14.1 33.01,68.11 ; LP14.1 31.79,66.89 ; LP14.1 33.01,65.67 ; LP14.1 34.23,66.89 ; 77.52,47.16 P2.21 ; P2.21 81.28,47.16 ; P2.21 79.4,48.14 ; P2.21 79.4,46.18 ; 26.94,3.81 J5.2 ; J5.2 28,4.88 ; J5.2 28,2.74 ; J5.2 29.07,3.81 ; P1.23 4.92,34.66 ; P1.23 3.59,33.73 ; P1.23 2.26,34.66 ; P1.23 3.59,35.59 ; LP8.1 69.85,49.48 ; LP8.1 69.85,47.04 ; LP8.1 68.63,48.26 ; LP8.1 71.07,48.26 ; 12.54,80 J13.7 11.71,82.22 ; 21.57,82.22 J13.10 20.74,80
  BOTTOM w0.203: v1(22.27,73.9) 21.96,73.58 C42.1 ; P1.2 v1(9.06,45.91) ; P1.17 v1(9.07,38.41) ; P1.11 v1(9.11,41.41) ; R127.1 v1(27.78,34.51) ; R36.1 v1(29.27,28.56) ; C23.2 v1(47.83,48.12) ; R35.1 v1(22.45,28.54) ; P1.8 v1(9.13,42.91) ; P1.5 v1(9.08,44.41) ; R86.1 v2(50.99,76.17)
  BOTTOM w0.254: v1(24.84,24.59) 24.66,24.77 R125.2 ; R126.2 24.69,23.01 v1(24.89,23.22)
  BOTTOM w0.305: C17.2 47.01,39.42 46.37,40.06 ; 46.37,40.06 v3(45.96,40.47) ; 46.37,40.06 46.37,39.19 C19.2
  BOTTOM w0.356: v3(42.91,43.52) 42.91,45.1 43.15,45.34 C10.2 ; C21.2 42.91,39.06 v3(42.91,40.47) 42.13,39.69 C22.2
  BOTTOM w0.381: C8.2 45.22,49.88 45.28,49.83 v1(45.82,49.83) ; D1.1 v1(16.89,18.2) ; C20.2 v1(50.67,37.9) ; C18.2 v1(40.92,46) ; R74.2 v1(80.07,16.82) ; C40.1 v1(27.46,73.44) ; C47.1 v1(24.28,72.31) ; R60.2 v1(44.32,14.74) ; R73.2 v1(41.88,2.36) ; Q2.2 v1(12.51,20.08) ; Q1.2 v1(12.54,23.59) ; R12.1 v1(15.25,20.58) ; C49.1 v1(24.39,70.36) ; C45.2 v1(24.36,71.17) ; R75.1 v1(66.58,20.27) ; C41.1 v1(28.27,73.35) ; C46.1 v1(24.24,73.15) ; R69.2 v1(59.43,22.61) ; R64.2 v1(58.98,2.49) ; C9.2 v1(40.74,37.4) ; R62.2 v1(51,2.29) ; R70.2 v1(52.69,14.6)
  vias: v1(44.38,76.65) v1(44.38,75.89) v1(44.38,75.13) v1(44.38,74.37) v1(45.14,76.65) v1(45.14,74.37) v1(45.9,76.65) v1(45.9,74.37) v1(46.67,76.65) v1(46.67,75.89) v1(46.67,75.13) v1(46.67,74.37) v2(51.81,75.4) v2(51.81,74.89) v2(51.81,74.38) v2(52.32,75.4) v2(52.32,74.38) v2(52.83,75.4) v2(52.83,74.89) v2(52.83,74.38) v3(42.91,42.5) v3(42.91,41.49) v3(43.67,43.52) v3(43.67,40.47) v3(45.19,43.52) v3(45.19,40.47) v3(45.96,43.52) v3(45.96,42.5) v3(45.96,41.49)
VCC_3P3V: length 25.7
  TOP w0.203: U3.5 v1(75.53,58.07) ; U3.6 v1(75.52,57.12) ; U1.43 v1(44.2,46.55) ; U1.13 v2(41.7,37.27)
  TOP w0.381: R78.1 v1(77.21,53.94) ; R84.1 v1(50.96,79.54) ; C29.1 v1(73.33,57.88)
  TOP w0.508: LP5.1 49.61,83.01 ; LP5.1 48.39,81.79 ; LP5.1 50.83,81.79 ; LP5.1 49.61,80.57
  L4 w0.508: 49.61,80.57 LP5.1 ; LP5.1 48.39,81.79 ; LP5.1 50.83,81.79 ; LP5.1 49.61,83.01
  BOTTOM w0.203: R59.1 21.82,14.53 v1(21.82,14.32) ; C9.1 41.45,37.66 v2(41.7,37.27)
  BOTTOM w0.381: C10.1 44.2,45.88 v1(44.2,46.55) 44.81,47.03 C8.1 ; R63.1 v1(58.11,6.97) ; R68.1 v1(52.49,19.73) ; R58.1 v1(34.77,14.14) ; R72.1 v1(75.64,21.85) ; R61.1 v1(50,6.88) ; R71.1 v1(36.32,6.7) ; R66.1 v1(59.4,27.74) ; R57.1 v1(44.35,19.73)
  vias: v1(47.47,82.56) v1(47.47,82.05) v1(47.47,81.54) v1(47.98,82.56) v1(47.98,82.05) v1(47.98,81.54)
VDD_1P1V: length 20.6
  TOP w0.203: U1.14 42.2,37.47 v2(42.26,37.25) ; v1(47.66,37.36) 47.2,37.97 U1.24 ; U1.23 v1(46.71,37.27)
  TOP w0.381: U1.48 41.4,45.23 v1(40.93,45.23) ; R89.1 v1(43.09,70.53) ; v1(47.22,46.55) 47.21,46.41 47.2,45.53 U1.37
  TOP w0.508: 41.76,68.17 LP6.1 42.98,66.95
  L3 w0.508: 40.54,66.95 LP6.1 ; LP6.1 41.76,65.73 ; LP6.1 42.98,66.95 ; LP6.1 41.76,68.17
  BOTTOM w0.381: C17.1 47.45,37.65 47.52,37.65 v1(47.66,37.36) 47.66,38.33 C20.1 ; v1(46.71,37.27) 46.25,37.9 C19.1 ; C18.1 41.29,45.23 v1(40.93,45.23) ; C22.1 42.26,37.96 v2(42.26,37.25) 42.83,37.98 C21.1 ; v1(47.22,46.55) 47.23,46.41 C23.1
  vias: v1(44.18,70.51) v1(44.18,70) v1(44.18,69.49) v1(44.68,70.51) v1(44.68,70) v1(44.68,69.49)
ARC_OUT: length 27
  TOP w0.203: C6.1 24.97,30.87 24.97,29.28 24.46,28.77 24.46,27.69 24.02,27.25 LP3.1 21.38,27.02 v1(19.94,27.03)
  BOTTOM w0.203: P1.14 13.68,39.91 17.98,35.61 17.98,28.98 v1(19.94,27.03)
AUX_SRCN/ARC_OUT: length 36.7
  TOP w0.127: v2(43.72,46.88) 43.59,46.75 43.59,46.05 43.7,45.94 U1.44
  BOTTOM w0.127: v2(43.72,46.88) 43.59,47 43.59,49.76 41.88,51.46 38.39,51.46 35.62,48.69 35.62,46.86 25.71,36.96 25.71,33.99 LP1.1 24.58,31.3 C4.1
AUX_SRCP/SPDIF_IN: length 36.7
  TOP w0.127: U1.45 43.2,45.95 43.31,46.06 43.31,46.75 v2(43.18,46.88)
  BOTTOM w0.127: v2(43.18,46.88) 43.31,47.01 43.31,49.64 41.77,51.18 38.5,51.18 35.9,48.58 35.9,46.75 25.99,36.84 25.99,35.93 26.07,35.85 26.17,35.85 26.25,35.78 26.25,35.67 26.17,35.6 26.07,35.6 25.99,35.52 25.99,35.42 26.07,35.34 26.17,35.34 26.25,35.27 26.25,35.16 26.17,35.09 26.07,35.09 25.99,35.02 25.99,34.73 R127.2 25.99,34.29 25.99,34.04 LP2.1 27.18,31.31 C5.1
BOARD_3P3V: length 28
  TOP w0.203: U8.8 v1(20.04,64.03) ; R99.1 v1(23.3,65.11) ; U7.25 v1(28.07,75.48) ; R102.1 v1(24.84,65.14) ; R81.1 v1(51.41,79) ; R87.1 v1(50.57,79)
  TOP w0.381: R103.1 v1(17.79,68.78) ; R100.1 v1(22.3,58.97) ; L2.1 v1(38.2,81.68) ; L2.1 v1(36.47,82.64) ; L2.1 v1(36.47,80.59) ; U5.5 v1(47.21,73.14) ; C35.1 v1(47.75,70.6) ; C35.1 v1(49,71.68) ; C35.1 v1(46.51,71.68) ; U5.6 v1(48.73,74.24) ; R92.2 v1(18.2,74.4) ; U6.4 v1(37.76,77.79) ; U5.7 v1(48.72,74.87) ; U5.8 v1(48.71,75.53) ; C59.2 v1(21.01,64.84) ; R98.1 v1(32.03,73.66) ; R79.1 v1(79.92,65.21) ; U4.14 v1(54.5,74.6) ; U6.6 v1(35.02,77.8) ; v1(33.02,81.66) C58.1 v1(34.21,82.72) ; U5.10 v1(47.85,77.45) ; R88.1 v1(48.34,79.83) ; U7.3 v1(20.07,73.56)
  BOTTOM w0.203: C41.2 28.27,75.29 v1(28.07,75.48) 27.69,75.1 C40.2 ; R85.2 v1(49.78,77.99) ; C42.2 20.62,73.56 v1(20.07,73.56)
  vias: v1(52.18,82.71) v1(52.18,82.2) v1(52.18,81.7) v1(52.18,81.19) v1(52.69,82.71) v1(52.69,82.2) v1(52.69,81.7) v1(52.69,81.19)
BOARD_5V: length 13.9
  TOP w0.254: R130.2 v1(76.78,32.5)
  TOP w0.356: v1(80.32,35.83) 80.25,35.9 79.59,35.9 79.58,35.91 P2.18
  TOP w0.381: R82.2 v1(38.9,75.75)
  L4 w0.508: 31.84,71.26 LP12.1 ; LP12.1 33.06,72.48 ; LP12.1 33.06,70.04 ; LP12.1 34.28,71.26
  BOTTOM w0.203: R11.2 v1(9.27,18.92) ; R104.1 v1(14.57,37.9)
  BOTTOM w0.254: R17.2 21.98,25.26 v1(21.59,24.87)
  BOTTOM w0.381: v1(74.93,38.51) R45.2 ; R46.2 v1(75.04,35.79) ; R10.2 v1(16.44,12.92) ; R16.2 v1(20.99,22.49)
  vias: v1(36.19,74.82) v1(36.95,74.82)
BOARD_IN: length 5.7
  TOP w0.508: 61.37,69.32 SW2.2 ; SW2.2 62.79,70.74 ; SW2.2 61.37,72.16 ; SW2.2 59.94,70.74
EN1P2: length 1.9
  TOP w0.203: R88.2 C37.1 46.79,78.99 U5.11
EQ_SEL_A0: length 21.3
  TOP w0.203: J12.2 48.51,21.23 48.51,27.74 45.7,30.55 U1.21
EQ_SEL_HI: length 1.8
  BOTTOM w0.203: R68.2 51.98,21.65 51.95,21.62 J12.1
EQ_SEL_LO: length 2
  BOTTOM w0.203: R70.1 51.64,16.54 51.63,16.54 J12.3
FB_3PT3V: length 2.1
  TOP w0.203: U4.5 v1(50.14,75.6)
  BOTTOM w0.203: v1(50.14,75.6) 50.23,76.05 R86.2 50.37,76.19 R85.1
HDMI_CEC_SNK: length 97.2
  TOP w0.203: P2.13 v1(79.93,38.41)
  BOTTOM w0.203: v1(79.93,38.41) 80.6,38.41 82.4,40.21 82.4,48.23 80.01,50.62 72.31,50.62 64.85,58.09 29.72,58.09 16.13,44.5 16.13,42.47 14.07,40.41 P1.13
HDMI_IN_5V: length 2.2
  BOTTOM w0.203: P1.18 12.24,37.91 12.26,37.9 R104.2
HDMI_SCL_SRC: length 105.3
  TOP w0.127: U1.38 46.59,45.65 46.59,46.75 v2(46.72,46.88) ; v1(19.96,24.74) v1(19.96,23.06) ; v2(76.63,37.43) 76.76,37.3 78.29,37.3 P2.15
  BOTTOM w0.127: v2(76.63,37.43) 76.5,37.29 76.47,37.29 76.46,37.28 76.11,37.28 R45.1 75.75,37.3 73.27,37.3 67.51,43.05 67.51,45.34 65.23,47.62 62.59,47.62 62.46,47.75 ; 62.46,47.75 62.33,47.62 61.63,47.62 61.56,47.7 61.56,47.75 61.48,47.83 61.38,47.83 61.3,47.75 61.3,47.7 61.23,47.62 61.13,47.62 61.05,47.7 61.05,47.75 60.98,47.83 60.87,47.83 60.8,47.75 60.8,47.7 60.72,47.62 58.18,47.62 55.97,45.42 47.05,45.42 46.58,45.88 46.58,46.74 v2(46.72,46.88) 46.59,47 46.59,53.92 43.74,56.77 32.92,56.77 21.08,44.93 21.08,25.58 20.69,25.18 20.25,25.18 19.96,24.89 v1(19.96,24.74) ; 62.46,47.75 LP10.1 ; R124.2 v1(19.96,23.06)
HDMI_SCL_SRC_IN: length 26.6
  BOTTOM w0.127: P1.15 10.43,39.3 8.64,39.3 8.05,38.71 8.05,36.96 8.86,36.14 11.43,36.14 12.22,35.36 12.22,28.47 16.88,23.81 20.46,23.81 R124.1
HDMI_SDA_SRC: length 105.2
  TOP w0.127: U1.39 46.31,45.65 46.31,46.75 v2(46.18,46.88) ; P2.16 78.3,37.02 76.76,37.02 v2(76.63,36.89)
  BOTTOM w0.127: v2(76.63,36.89) 76.53,37 76.09,37 76.04,36.95 R46.1 75.74,37.02 73.15,37.02 67.23,42.93 67.23,45.22 65.11,47.35 62.59,47.35 62.46,47.22 ; 62.46,47.22 62.33,47.35 58.29,47.35 56.08,45.14 46.93,45.14 46.3,45.76 46.3,46.76 v2(46.18,46.88) 46.31,47 46.31,53.8 43.62,56.49 33.03,56.49 21.36,44.82 21.36,28.73 21.44,28.66 21.67,28.66 21.74,28.58 21.74,28.48 21.67,28.4 21.44,28.4 21.36,28.33 21.36,28.22 21.44,28.15 21.67,28.15 21.74,28.08 21.74,27.97 21.67,27.9 21.44,27.9 21.36,27.82 21.36,27.72 21.44,27.64 21.67,27.64 21.74,27.57 21.74,27.46 21.67,27.39 21.44,27.39 21.36,27.31 21.36,27.21 21.44,27.13 21.67,27.13 21.74,27.06 21.74,26.95 21.67,26.88 21.44,26.88 21.36,26.81 21.36,26.7 21.44,26.63 21.67,26.63 21.74,26.55 21.74,26.45 21.67,26.37 21.44,26.37 21.36,26.3 21.36,26.19 21.44,26.12 21.67,26.12 21.74,26.04 21.74,25.94 21.67,25.86 21.44,25.86 21.36,25.79 21.36,25.25 20.95,24.84 R123.2 ; 62.46,47.22 LP11.1
HDMI_SDA_SRC_IN: length 26.6
  BOTTOM w0.127: P1.16 10.43,39.02 8.76,39.02 8.33,38.59 8.33,37.07 8.98,36.42 11.55,36.42 12.5,35.47 12.5,28.59 16.99,24.09 18.52,24.09 18.6,24.17 18.6,24.26 18.67,24.33 18.78,24.33 18.85,24.26 18.85,24.17 18.93,24.09 19.03,24.09 19.11,24.17 19.11,24.26 19.18,24.33 19.28,24.33 19.36,24.26 19.36,24.17 19.43,24.09 19.54,24.09 19.61,24.17 19.61,24.26 19.69,24.33 19.79,24.33 19.87,24.26 19.87,24.17 19.94,24.09 20.46,24.09 R25.2
HDMI_SEL#_TEST_A1: length 23.3
  TOP w0.203: U1.27 v1(49.08,40.16)
  BOTTOM w0.203: v1(49.08,40.16) 53.44,40.16 63.18,30.43 63.18,28.62 J7.2
HPD_SNK: length 36.2
  TOP w0.203: P2.19 v1(76.75,35.41) 76.75,34.98 76.76,34.97 R130.1 R129.1 ; U1.33 v1(49.08,43.16)
  BOTTOM w0.203: v1(76.75,35.41) 75.98,34.65 66.95,34.65 LP13.1 58.44,43.16 v1(49.08,43.16)
HPD_SRC: length 44.8
  BOTTOM w0.203: R5.1 16.98,19.56 17.01,19.6 J1.1 21.59,19.6 21.83,19.84 34.57,19.84 37.59,22.86 37.59,32.81 35.72,34.69 35.72,39.04 38.06,41.38 R131.2
HPD_SRC_CONN: length 107.2
  TOP w0.203: J1.3 17.98,13.55 17.98,13.55 17.98,11.07 15.42,8.51 15.42,2.57 16.99,0.99 66.19,0.99 75.03,9.83 75.03,25.07 75.95,25.98 R129.2
  BOTTOM w0.203: J1.3 17.94,14.56 R10.1 15.98,14.56 15.97,14.54 14.32,14.54 R13.2 13.91,16.52 14.01,16.62 D1.3
HPD_SRC_HDMI_RX_CONN: length 26.4
  TOP w0.203: J1.2 15.58,17.06 13.54,19.1 13.54,37.03 13.16,37.41 v1(12.03,37.41)
  BOTTOM w0.203: P1.19 v1(12.03,37.41)
I2C_EN_HI: length 2
  BOTTOM w0.203: R57.2 43.86,21.7 43.85,21.7 J3.1
I2C_EN_LO: length 2
  BOTTOM w0.203: R60.1 43.84,16.6 43.82,16.62 J3.3
I2C_EN_PIN: length 24.7
  TOP w0.203: U1.10 v1(39.81,40.16)
  BOTTOM w0.203: v1(39.81,40.16) 39.25,39.46 39.25,37.98 39.95,37.28 42.26,34.97 42.26,24.97 40.81,23.52 40.81,20.72 J3.2
IN_CLKN: length 31.4
  TOP w0.127: v2(12.44,41.14) 12.56,41.27 22.19,41.27 24.19,39.27 40.71,39.27 U1.12
  BOTTOM w0.127: v2(12.44,41.14) 12.31,41.27 11.89,41.27 11.68,41.05 11.67,41.05 11.52,40.91 P1.12
IN_CLKP: length 31.6
  TOP w0.127: v2(12.44,41.68) 12.56,41.55 13.37,41.55 13.61,41.79 13.94,41.79 14.18,41.55 22.31,41.55 24.31,39.55 40.71,39.55 U1.11
  BOTTOM w0.127: P1.10 11.53,41.91 11.68,41.77 11.68,41.77 11.89,41.55 12.31,41.55 v2(12.44,41.68)
IN_D0N: length 31.5
  TOP w0.127: v2(12.44,42.64) 12.56,42.77 12.98,42.77 13.1,42.9 13.54,42.9 13.67,42.77 23.38,42.77 25.38,40.77 40.71,40.77 U1.9
  BOTTOM w0.127: P1.9 11.52,42.41 11.67,42.56 11.68,42.56 11.89,42.77 12.31,42.77 v2(12.44,42.64)
IN_D0P: length 31.6
  TOP w0.127: v2(12.44,43.18) 12.56,43.05 12.86,43.05 13.1,43.29 13.56,43.29 13.8,43.05 23.5,43.05 25.5,41.05 40.71,41.05 U1.8
  BOTTOM w0.127: v2(12.44,43.18) 12.31,43.05 11.89,43.05 11.68,43.27 11.67,43.27 11.53,43.41 P1.7
IN_D1N: length 31.6
  TOP w0.127: U1.6 40.71,42.27 26.24,42.27 24.25,44.27 13.71,44.27 13.47,44.04 13.12,44.04 12.89,44.27 12.56,44.27 v2(12.44,44.14)
  BOTTOM w0.127: P1.6 11.52,43.91 11.67,44.05 11.68,44.05 11.89,44.27 12.32,44.27 12.44,44.15 v2(12.44,44.14)
IN_D1P: length 31.6
  TOP w0.127: U1.5 40.71,42.55 26.36,42.55 24.36,44.55 13.59,44.55 13.4,44.36 13.2,44.36 13.01,44.55 12.56,44.55 v2(12.44,44.68)
  BOTTOM w0.127: v2(12.44,44.68) 12.31,44.55 11.89,44.55 11.68,44.76 11.67,44.76 11.53,44.91 P1.4
IN_D2N: length 31.6
  TOP w0.127: U1.3 40.71,43.77 26.84,43.77 24.84,45.77 13.52,45.77 13.29,45.54 13.1,45.54 12.87,45.77 12.56,45.77 v2(12.44,45.64)
  BOTTOM w0.127: v2(12.44,45.64) 12.31,45.77 11.89,45.77 11.68,45.55 11.67,45.55 11.53,45.41 P1.3
IN_D2P: length 31.5
  TOP w0.127: v2(12.44,46.18) 12.56,46.05 12.98,46.05 13.05,45.98 13.29,45.98 13.37,46.05 24.96,46.05 26.96,44.05 40.71,44.05 U1.2
  BOTTOM w0.127: v2(12.44,46.18) 12.31,46.05 11.89,46.05 11.68,46.27 11.67,46.27 11.53,46.41 P1.1
OE: length 39.9
  TOP w0.203: R77.1 75.37,54.86 C26.1 74.88,54.85 74.88,54.85 70.83,54.85 69.25,56.44 50.23,56.44 44.7,50.9 U1.42
OUT_CLKN: length 30.5
  TOP w0.127: U1.25 48.13,39.16 48.24,39.27 74.43,39.27 76.99,39.27 77.35,38.91 P2.12
OUT_CLKP: length 30.5
  TOP w0.127: P2.10 77.35,39.91 76.99,39.55 74.55,39.55 74.55,39.55 48.23,39.55 48.11,39.66 U1.26
OUT_D0N: length 30.5
  TOP w0.127: P2.9 77.37,40.41 77.01,40.77 74.47,40.77 74.46,40.77 48.19,40.77 U1.28
OUT_D0P: length 30.5
  TOP w0.127: U1.29 48.19,41.05 74.35,41.05 77.02,41.05 77.38,41.41 P2.7
OUT_D1N: length 30.5
  TOP w0.127: U1.31 48.19,42.27 50.88,42.27 77.03,42.27 77.4,41.91 P2.6
OUT_D1P: length 30.5
  TOP w0.127: P2.4 77.4,42.91 77.04,42.55 51,42.55 51,42.55 48.19,42.55 U1.32
OUT_D2N: length 30.5
  TOP w0.127: U1.34 48.19,43.77 75.02,43.77 77.05,43.77 77.41,43.41 P2.3
OUT_D2P: length 30.5
  TOP w0.127: U1.35 48.19,44.05 74.9,44.05 77.05,44.05 77.41,44.41 P2.1
PB_MANUAL_RESET: length 14
  TOP w0.203: SW1.3 R80.1 77.88,60.54 77.9,60.52 77.9,60.27 77.22,59.59 U3.3 ; SW1.3 SW1.4 ; SW1.3 79.91,63.31 ; C27.1 79.91,63.31 ; 79.91,63.31 R79.2
PRE_SEL: length 36.8
  TOP w0.203: U1.20 45.2,17.02 J15.2
PRE_SEL_HI: length 2
  BOTTOM w0.203: J15.1 57.11,8.61 57.13,8.59 R63.2
PRE_SEL_LO: length 2.2
  BOTTOM w0.203: J15.3 57.85,3.53 57.85,3.54 R64.1
PWRIN_SW: length 15
  TOP w0.508: 61.37,64.62 SW2.1 ; SW2.1 61.37,67.46 ; SW2.1 62.79,66.04 ; SW2.1 59.94,66.04 ; 70.43,69.84 J9.1 ; J9.1 75.11,69.84 ; J9.1 72.77,67.5 ; J9.1 72.77,72.17
REG_PG: length 0.8
  TOP w0.381: R80.2 v1(77.04,62.07)
  vias: v1(49.43,77.36) v1(49.43,76.8)
RSTIN: length 4.7
  TOP w0.203: R103.2 19.52,68.15 19.53,68.14 C52.2 21.1,67.36 21.98,68.24 U7.9
SCL_CTL: length 39.8
  TOP w0.203: U1.15 42.7,34.47 35.91,27.68 35.91,27.31 35.48,26.87 33.05,26.87 32.7,26.53 32.7,25.75 33.05,25.4 35.48,25.4 35.91,24.97 35.91,24.36 35.48,23.93 33.05,23.93 32.73,23.6 32.73,22.78 33.05,22.45 35.48,22.45 35.91,22.02 35.91,19.44 J4.2
  BOTTOM w0.203: J4.2 34.28,16.01 34.29,16.02 R58.2
SCL_CTL_USB: length 102.7
  TOP w0.203: U7.30 v1(24.07,77.6)
  BOTTOM w0.203: v1(24.07,77.6) 24.07,76.79 22.89,75.6 17.73,75.6 5.68,63.55 5.68,19.29 13.09,11.88 25.8,11.88 J4.1
SCL_SRC: length 46.1
  TOP w0.127: U1.46 42.59,45.65 42.59,48.27 v2(42.72,48.39)
  BOTTOM w0.127: R24.1 21.29,23.75 21.83,23.75 R16.1 22.25,23.74 23.86,23.74 R126.1 24.11,23.75 26.62,23.75 27.67,22.69 29.08,22.69 29.21,22.57 ; v2(42.72,48.39) 42.63,48.3 42.63,47.09 42.17,46.64 40.38,46.64 30.93,37.19 30.93,23.23 30.4,22.69 29.34,22.69 29.21,22.57 ; 29.21,22.57 LP15.1
SDA_CTL: length 39.7
  TOP w0.203: U1.16 43.2,34.02 37.05,27.87 37.05,18.47 33.29,14.71 26.55,14.71 25.25,16 J6.2
  BOTTOM w0.203: R59.2 22.72,16.02 22.75,16 J6.2
SDA_CTL_USB: length 94.4
  TOP w0.203: U7.29 v1(24.87,77.56)
  BOTTOM w0.203: v1(24.87,77.56) 24.87,76.64 23.16,74.93 17.76,74.93 6.3,63.47 6.3,19.5 13.47,12.33 18.33,12.33 20.32,14.32 20.32,16.84 22.01,18.54 J6.1
SDA_SRC: length 46.1
  TOP w0.127: U1.47 42.31,45.65 42.31,48.27 v2(42.18,48.39)
  BOTTOM w0.127: v2(42.18,48.39) 42.35,48.23 42.35,47.21 42.06,46.92 40.26,46.92 30.65,37.3 30.65,23.34 30.28,22.97 29.34,22.97 29.21,23.1 ; 29.21,23.1 29.08,22.97 27.79,22.97 26.73,24.03 25.62,24.03 25.54,24.11 25.54,24.23 25.47,24.3 25.36,24.3 25.29,24.23 25.29,24.11 25.21,24.03 24.1,24.03 R125.1 23.84,24.02 22.21,24.02 22.05,24.18 R17.1 21.86,24.03 21.41,24.03 R25.1 ; 29.21,23.1 LP16.1
SIG_EN: length 34.4
  TOP w0.203: J11.2 40.44,7.65 40.44,29.83 43.7,33.1 U1.17
SIG_EN_HI: length 2.4
  BOTTOM w0.203: R71.2 37.74,8.53 37.77,8.5 J11.1
SIG_EN_LO: length 2.3
  BOTTOM w0.203: J11.3 39.71,3.42 39.72,3.41 R73.1
SPDIF_IN: length 120.6
  TOP w0.203: R34.1 27.52,29.06 27.23,28.77 27.23,27.72 27.74,27.21 LP4.1 26.27,27.04 25.55,26.31 25.55,21.92 24.84,21.21 22.4,21.21 20.98,19.79 20.98,12.93 21.64,12.27 21.64,2.74 22.86,1.52 65.89,1.52 74.42,10.06 74.42,36.93 75.29,37.8 76.13,37.8 76.24,37.91 P2.14
SS1P2: length 1
  TOP w0.203: C38.1 44.19,78.88 U5.15
SWAP/POL: length 48.1
  TOP w0.203: U1.1 v1(39.77,44.66)
  BOTTOM w0.203: J17.2 45.66,5.9 39.59,11.96 39.59,31.79 36.36,35.02 36.36,37.72 40.7,42.06 40.7,43.86 v1(39.77,44.66)
SWAP_POL_HI: length 2.1
  BOTTOM w0.203: J17.1 48.85,8.44 48.86,8.45 R61.2
SWAP_POL_LO: length 2.3
  BOTTOM w0.203: R62.1 48.87,3.34 48.85,3.36 J17.3
TPS3808_CT: length 1.3
  TOP w0.203: U3.4 73.76,59.01 73.75,59 C28.1
TX_TERM_CTL: length 43.3
  TOP w0.203: U1.36 v1(49.08,44.66)
  BOTTOM w0.203: J14.2 76.82,21.17 76.81,21.16 74.36,21.16 66.62,28.9 66.62,32.11 57.65,41.08 50.3,41.08 48.41,42.98 48.41,44.04 v1(49.08,44.66)
TX_TERM_CTL_HI: length 2.1
  BOTTOM w0.203: R72.2 76.82,23.71 76.82,23.71 J14.1
TX_TERM_CTL_LO: length 2.3
  BOTTOM w0.203: J14.3 79.35,18.63 R74.1
USB_5V: length 6.3
  TOP w0.203: U16.1 16.04,75.57 16.08,75.62 16.08,75.67 v1(16.18,75.77)
  BOTTOM w0.508: SW2.3 62.79,75.44 ; SW2.3 61.37,74.02 ; SW2.3 61.37,76.86 ; SW2.3 59.94,75.44
  vias: v1(14.03,75.04) v1(14.03,74.53) v1(14.54,75.04) v1(14.54,74.53) v1(15.05,75.04) v1(15.05,74.53)
VSADJ: length 33.3
  TOP w0.203: J8.2 66.38,21.88 57.61,21.88 46.2,33.29 U1.22
X1: length 3.5
  TOP w0.203: U7.27 26.47,77.98 26.37,78.08 C51.1 26.37,79.16 26.33,79.2 Y1.3
X2: length 6
  TOP w0.203: Y1.1 28.56,81.75 27.87,81.07 27.53,80.72 C50.1 27.53,78.09 27.27,77.83 U7.26
N16782838: length 2.2
  TOP w0.203: R77.2 77.2,55.73 R78.2 77.22,56.59 77.22,56.59 U3.1
N16874758: length 2.2
  BOTTOM w0.203: R66.2 59.85,29.53 59.86,29.52 J7.1
N16874763: length 2.1
  BOTTOM w0.203: J7.3 60,24.44 59.99,24.43 R69.1
N16881139: length 7.8
  TOP w0.203: J6.3 25.46,11.71 J5.3
N16881148: length 9
  BOTTOM w0.203: J5.1 32.48,10.82 J4.3
N16883754: length 2.2
  BOTTOM w0.203: J8.1 67.07,22 67.06,22 R75.2
N16883759: length 12.3
  TOP w0.203: R76.2 R76.1 64.9,10.62 64.87,10.64 64.87,14.45 65.78,15.36 R115.1 67.23,15.36 J8.3
N16887406: length 1.5
  TOP w0.203: U7.12 24.87,67.28 24.84,67.25 R102.2
N16892757: length 5.9
  BOTTOM w0.203: R5.2 14.41,19.56 R12.2 12.15,21.79 11.47,21.79 10.61,22.64 Q1.1
N16892765: length 4.2
  BOTTOM w0.203: Q2.1 11.01,19.62 11.01,20.01 11.56,20.57 Q1.3 10.94,20.67 10.87,20.74 R11.1
N16892877: length 2.8
  BOTTOM w0.203: Q2.3 11.55,17.15 12.87,15.83 R13.1
N16906083: length 3.7
  TOP w0.203: C7.1 v1(29.65,30.87)
  BOTTOM w0.203: R36.2 28.46,30.84 C5.2 v1(29.65,30.87)
N16910161: length 4.1
  TOP w0.203: v1(22.89,32.13) 23.28,31.74 C6.2
  BOTTOM w0.203: R35.2 23.27,30.11 23.28,30.12 C4.2 23.28,31.74 v1(22.89,32.13)
N16916452: length 7.8
  TOP w0.203: U7.11 24.07,64.7 24.56,64.21 JP1.1 26.03,63.25 R122.1
N16916458: length 7.1
  TOP w0.203: U8.6 21.81,60.68 21.82,60.67 R100.2 23.56,60.67 23.6,60.71 JP1.2 26.14,60.71 R122.2
N16916991: length 14.6
  TOP w0.203: U7.10 23.27,67.27 23.29,67.25 R99.2 21.7,66.76 20.78,65.84 18.69,65.84 18.21,65.35 18.21,59.93 18.73,59.41 U8.5
N16919313: length 2.6
  TOP w0.203: U7.5 v1(20.1,71.96)
  BOTTOM w0.203: R94.1 21.11,72.07 21,71.96 v1(20.1,71.96)
N16919318: length 8.9
  TOP w0.127: R96.1 16.58,73.2 16.58,72.11 17.78,70.9 20.89,70.9 U7.6
  TOP w0.203: U7.6 v1(22.14,71.16)
  BOTTOM w0.203: C45.1 22.66,71.16 v1(22.14,71.16) 21.72,71.16 R94.2
N16919400: length 8.9
  TOP w0.127: R95.1 16.3,73.2 16.3,71.99 17.67,70.62 19.84,70.62 19.92,70.55 19.92,70.53 19.99,70.46 20.1,70.46 20.17,70.53 20.17,70.55 20.25,70.62 20.89,70.62 U7.7
  TOP w0.203: U7.7 v1(22.15,70.36)
  BOTTOM w0.203: C49.2 22.65,70.36 v1(22.15,70.36)
N16919998: length 1.5
  TOP w0.203: R101.1 20.19,75.15 20.21,75.16 U7.1
N16928867: length 1.4
  TOP w0.203: C7.2 26.91,30.71 R34.2
N16965307: length 2
  TOP w0.203: R83.1 R120.1 49.96,74.59 49.98,74.6 U4.7
N16965335: length 1.4
  TOP w0.203: U4.9 51.14,73.38 C34.1
N16968702: length 2.4
  TOP w0.203: U7.24 U7.23 30.49,74.36 30.49,74.37 R98.2
N16982334: length 2.1
  TOP w0.203: U8.7 21.6,61.95 21.62,61.96 R121.1
N17019193: length 1.7
  TOP w0.203: U1.4 v1(39.71,43.16)
  BOTTOM w0.203: R131.1 39.71,43.16 v1(39.71,43.16)
N17024118: length 5.7
  TOP w0.127: J13.2 16.18,79.16 16.18,76.71 U16.5 16.04,76.5 15.66,76.12 15.66,74.46 R95.2
N17024121: length 5.7
  TOP w0.127: R96.2 16.83,74.61 17.04,74.81 U16.3 17.04,75.61 16.46,76.19 16.46,79.16 J13.3
N169633680: length 1.2
  TOP w0.381: R82.1 38.15,73.57 38.16,73.56 D2.1

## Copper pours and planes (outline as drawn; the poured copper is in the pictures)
GND on L2, L5: 0.51,0.51 88.44,0.51 88.44,83.36 0.51,83.36
VCC_3P3V on TOP: 51.26,79.44 51.26,82.13 50.3,83.09 47.44,83.09 47.08,82.74 47.08,80.45 48.74,80.45 49.76,79.44
VCC_3P3V on L4: 35.51,5.74 30.34,10.91 22.68,10.91 20.05,13.54 20.05,16.96 22.8,19.72 22.8,28.59 20.05,31.35 20.05,44.38 41.49,65.82 41.49,83.36 88.44,83.36 88.44,50.52 73.58,50.52 70.7,47.64 70.7,33.53 77.41,26.81 77.41,15.26 67.9,5.74 ; 1 cut-out
VDD_1P1V on TOP: 42.73,71.5 44.33,71.5 45.18,70.65 45.18,68.39 42.59,65.79 40.52,65.79 40.52,68.86 42.69,71.03 42.69,71.46
VDD_1P1V on L3: 38.72,36.36 38.72,73.05 44.79,73.05 44.79,52.78 50.2,47.37 50.2,36.36
BOARD_1P1V on TOP: 41.53,75.9 41.53,75.03 40.92,75.03 40.92,73.43 40.94,73.41 42.7,73.41 42.72,73.38 42.72,71.96 44.25,71.96 44.37,72.09 44.37,73.61 44.27,73.71 43.71,73.71 43.61,73.81 43.61,75.64 43.54,75.72 42.32,75.72 42.14,75.9
BOARD_3P3V on TOP: 54.94,83.08 54.94,79.2 51.77,79.2 51.77,83.08
BOARD_3P3V on L3: 0.51,0.51 0.51,83.36 88.44,83.36 88.44,0.51 ; 2 cut-outs
BOARD_5V on TOP: 37.26,76.09 37.26,74.49 37.08,74.31 37.08,72.74 35.76,72.74 35.71,72.79 35.71,74.76 36.28,75.34 36.28,76.08 36.29,76.09
BOARD_5V on L4: 0.51,0.51 0.51,83.36 40.47,83.36 40.47,66.24 19.03,44.8 19.03,31.01 19.6,31.01 22.28,28.33 22.28,20.16 19.03,16.9 19.03,13.12 22.26,9.89 29.92,9.89 35.09,4.73 68.32,4.73 78.43,14.84 78.43,27.23 71.71,33.95 71.71,47.22 74,49.51 88.44,49.51 88.44,0.51
BOARD_IN on TOP: 51.89,73.81 51.89,72.21 51.23,71.55 51.23,69.98 53.64,69.98 54.53,69.09 62.2,69.09 62.97,69.85 62.97,71.65 62.13,72.49 54.89,72.49 54.28,73.1 54.28,74.27 53.34,74.27 53.31,74.24 53.31,73.81
FB_1PT2V on TOP: 40.56,76.96 40.56,76.43 40.61,76.38 42.04,76.38 42.29,76.63 43.61,76.63 43.61,77.04 40.64,77.04
PWRIN_SW on TOP: 59.54,67.94 59.54,64.26 60.02,63.78 72.26,63.78 75.46,66.98 75.46,71.81 74.47,72.8 71.78,72.8 66.93,67.94
REG_PG on TOP: 47.37,76 49.78,76 49.78,77.01 49.81,77.04 51.41,77.04 51.41,75.9 51.66,75.9 51.69,75.92 51.69,77.57 51.64,77.62 49.08,77.62 49.05,77.59 49.06,77.59 49.06,76.87 48.56,76.38 47.4,76.38 47.37,76.35
REG_PG on L4: 54.39,78.72 48,78.72 46.95,77.67 46.95,75.21 61.31,60.85 78.02,60.85 79,61.83 79,63.55 76.62,65.94 69.14,65.94 69.1,65.91 67.21,65.91
USB_5V on TOP: 15.13,80.22 15.13,78.58 14.32,77.77 13.77,77.77 13.77,74.25 15.12,74.25 15.32,74.45 15.32,76.68 15.54,76.9 15.54,80.22
USB_5V on BOTTOM: 13.77,76.66 13.77,74.36 13.87,74.26 15.73,74.26 18.45,76.98 21.58,76.98 23.77,79.16 53.89,79.16 59.89,73.16 62.91,73.16 64.91,75.16 64.91,79.41 61.26,83.06 23.58,83.06 16.82,77.2 14.31,77.2
N16962991 on TOP: 35.36,80.09 35.36,78.66 35.65,78.37 36.1,78.37 36.23,78.23 36.23,77.47 36.27,77.43 36.68,77.43 36.69,77.44 36.69,78.22 36.93,78.46 37.49,78.46 37.62,78.59 37.62,80.09 37.62,80.1 35.36,80.1
N16965311 on TOP: 51.89,75.9 53.21,75.9 53.24,75.92 53.24,76.89 53.62,77.27 54.94,77.27 54.99,77.32 54.99,78.61 54.91,78.69 52.86,78.69 52.76,78.59 52.76,77.19 52.35,76.78 51.89,76.78

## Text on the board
BOTTOM: LAYER 6 - BOTTOM
Board Geometry/Soldermask Bottom: LAYER 8 - SOLDERMASK BOTTOM
Package Geometry/Pastemask Bottom: LAYER 10 - SOLDERPASTE BOTTOM
Ref Des/Silkscreen Bottom: FOR EVALUATION ONLY: | NOT FCC APPROVED FOR RESALE | LAYER 12 - SILKSCREEN BOTTOM
TOP: LAYER 1 - TOP
Board Geometry/Soldermask Top: LAYER 7 - SOLDERMASK TOP
Package Geometry/Pastemask Top: LAYER 9 - SOLDERPASTE TOP
Ref Des/Silkscreen Top: BOARD | 5V | OUT2 | ARC | OUT | SPDIF | SDA_USB | SDA_AAR | SDA | IN2 | IN | GND | SCL_USB | SCL_AAR | SCL | VDD_1P1V | SIG_EN | LO | HI | VCC_3P3V | I2C_EN | PIN | /POL | SWAP | EQ_SEL | A0 | PRE_SEL | TEST/A1 | VSADJ | POT | DEFAULT | BOARD_RESET | TX_TERM_CTL | USB 5V | WALL | OFF | TMDS171RGZEVM INT028 REV A | 6590487 | LAYER 11 - SILKSCREEN TOP
L2: LAYER 2 - GND
L3: LAYER 3 - PWR
L4: LAYER 4 - PWR
L5: LAYER 5 - GND
